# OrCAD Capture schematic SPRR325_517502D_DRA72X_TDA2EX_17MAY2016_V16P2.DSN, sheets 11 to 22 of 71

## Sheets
11 SH15 - SoC CLOCKS: size B; rev: A
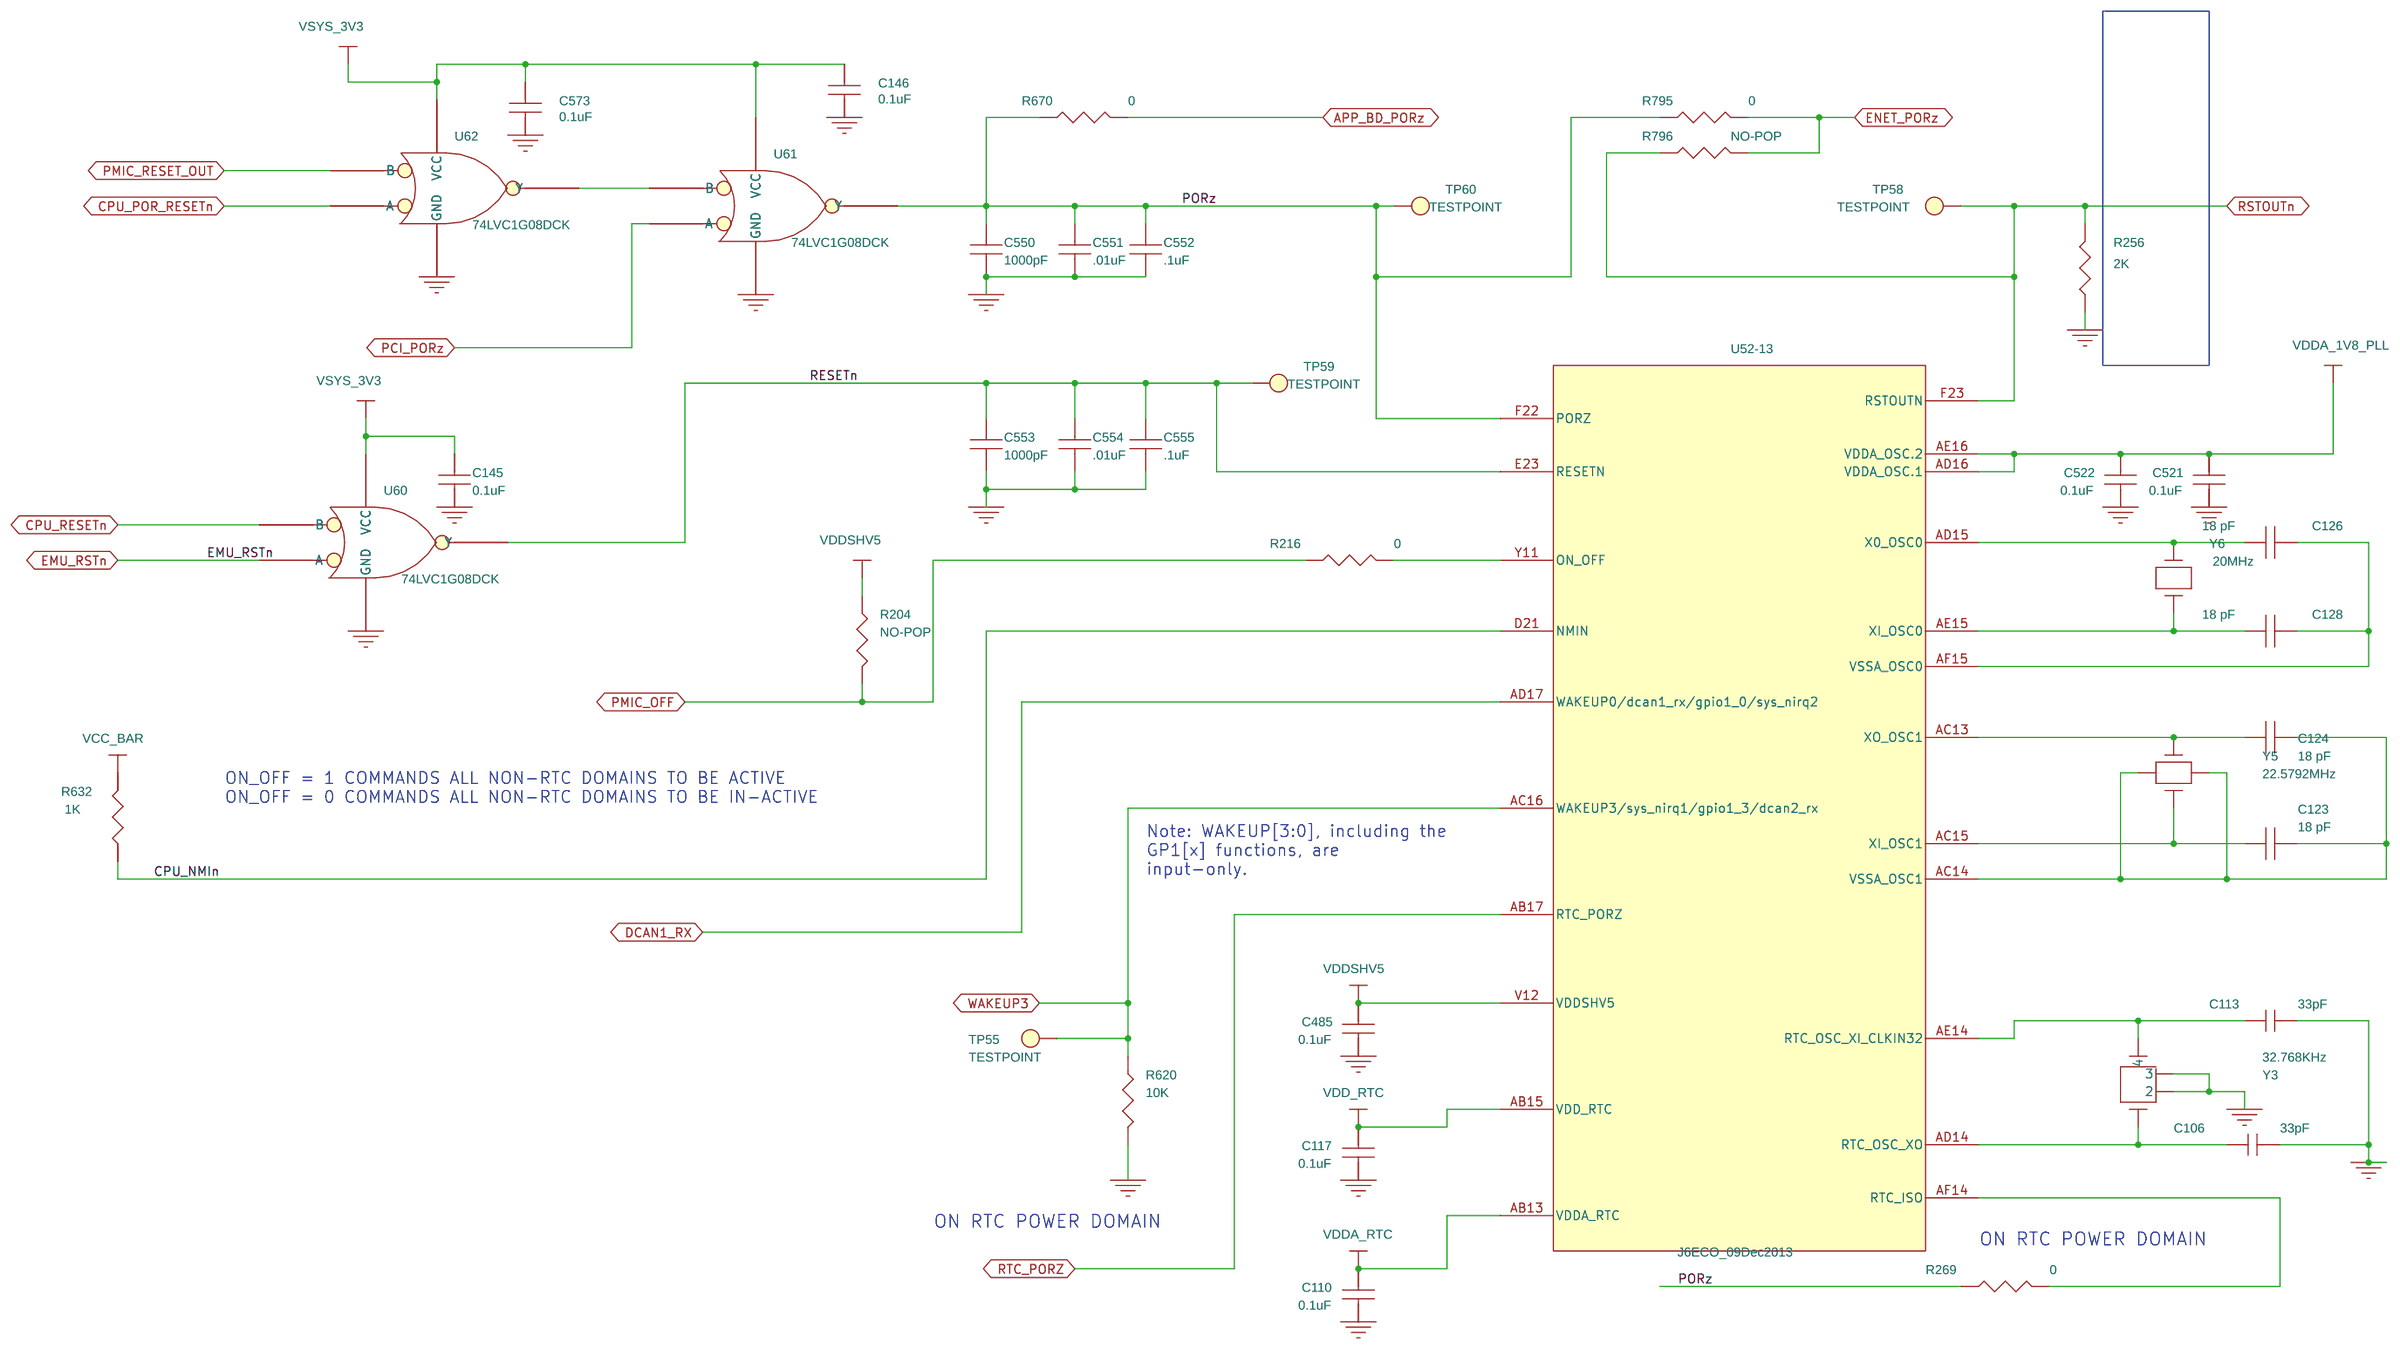
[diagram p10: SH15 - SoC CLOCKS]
12 SH16 - SoC INTERNAL LDOS: size B; rev: A
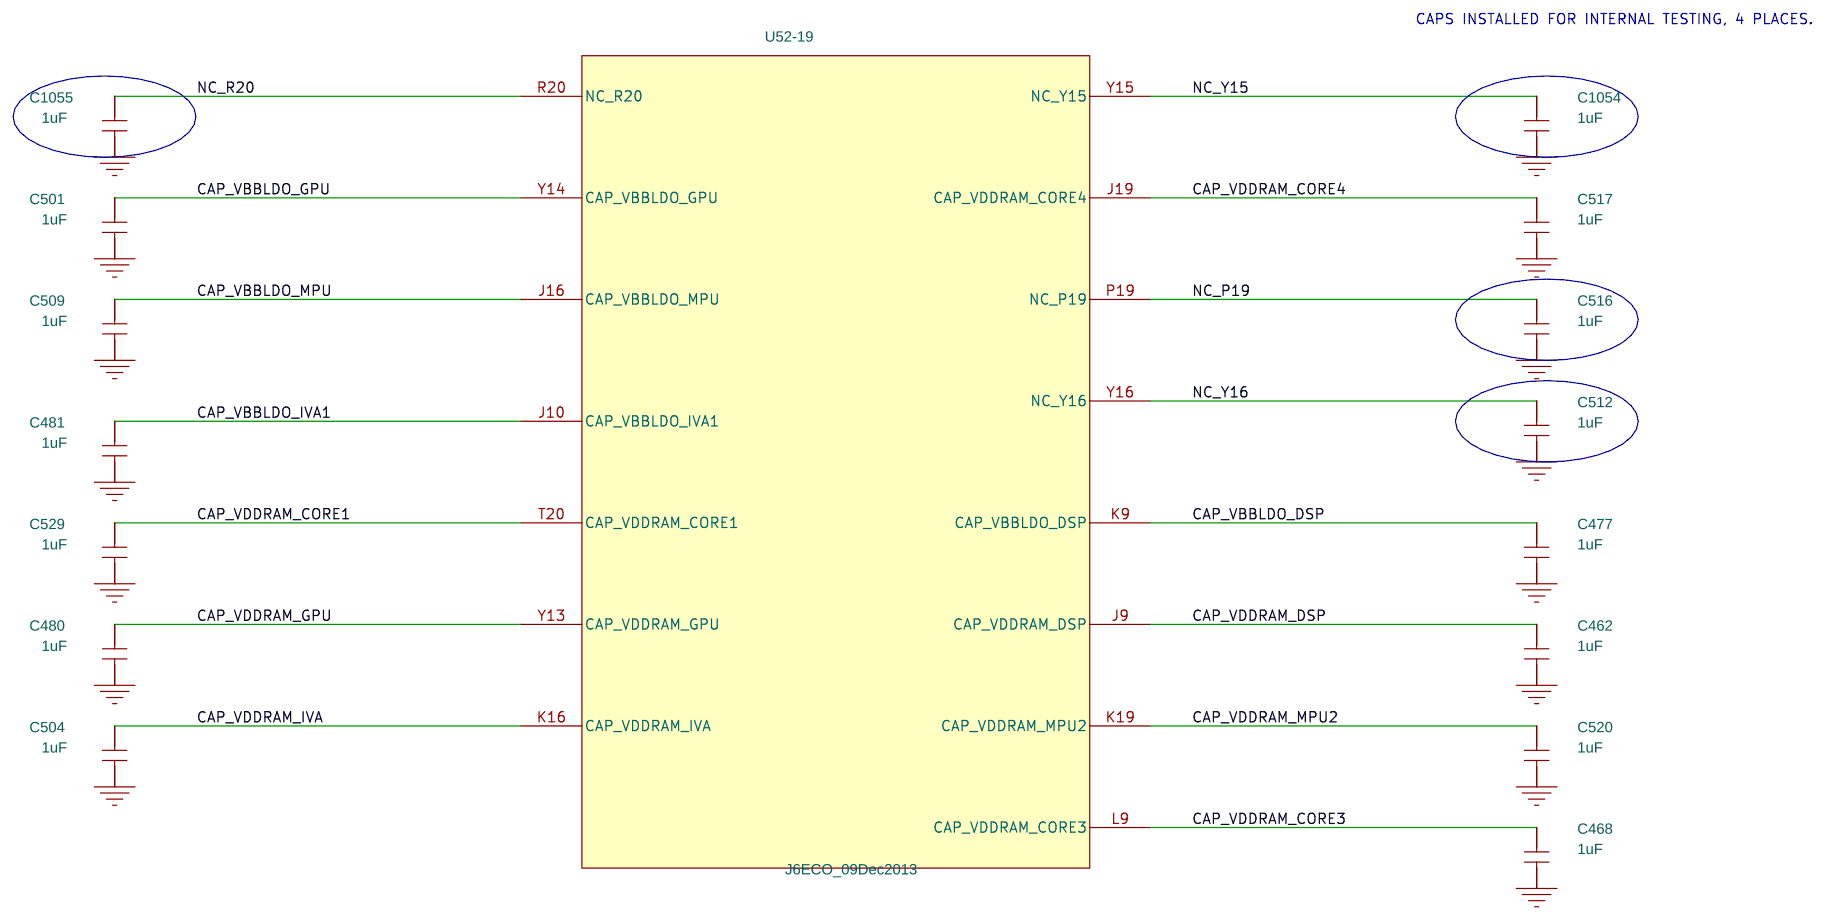
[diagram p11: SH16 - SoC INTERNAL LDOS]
13 SH17 - SoC IO POWER: size B; rev: A
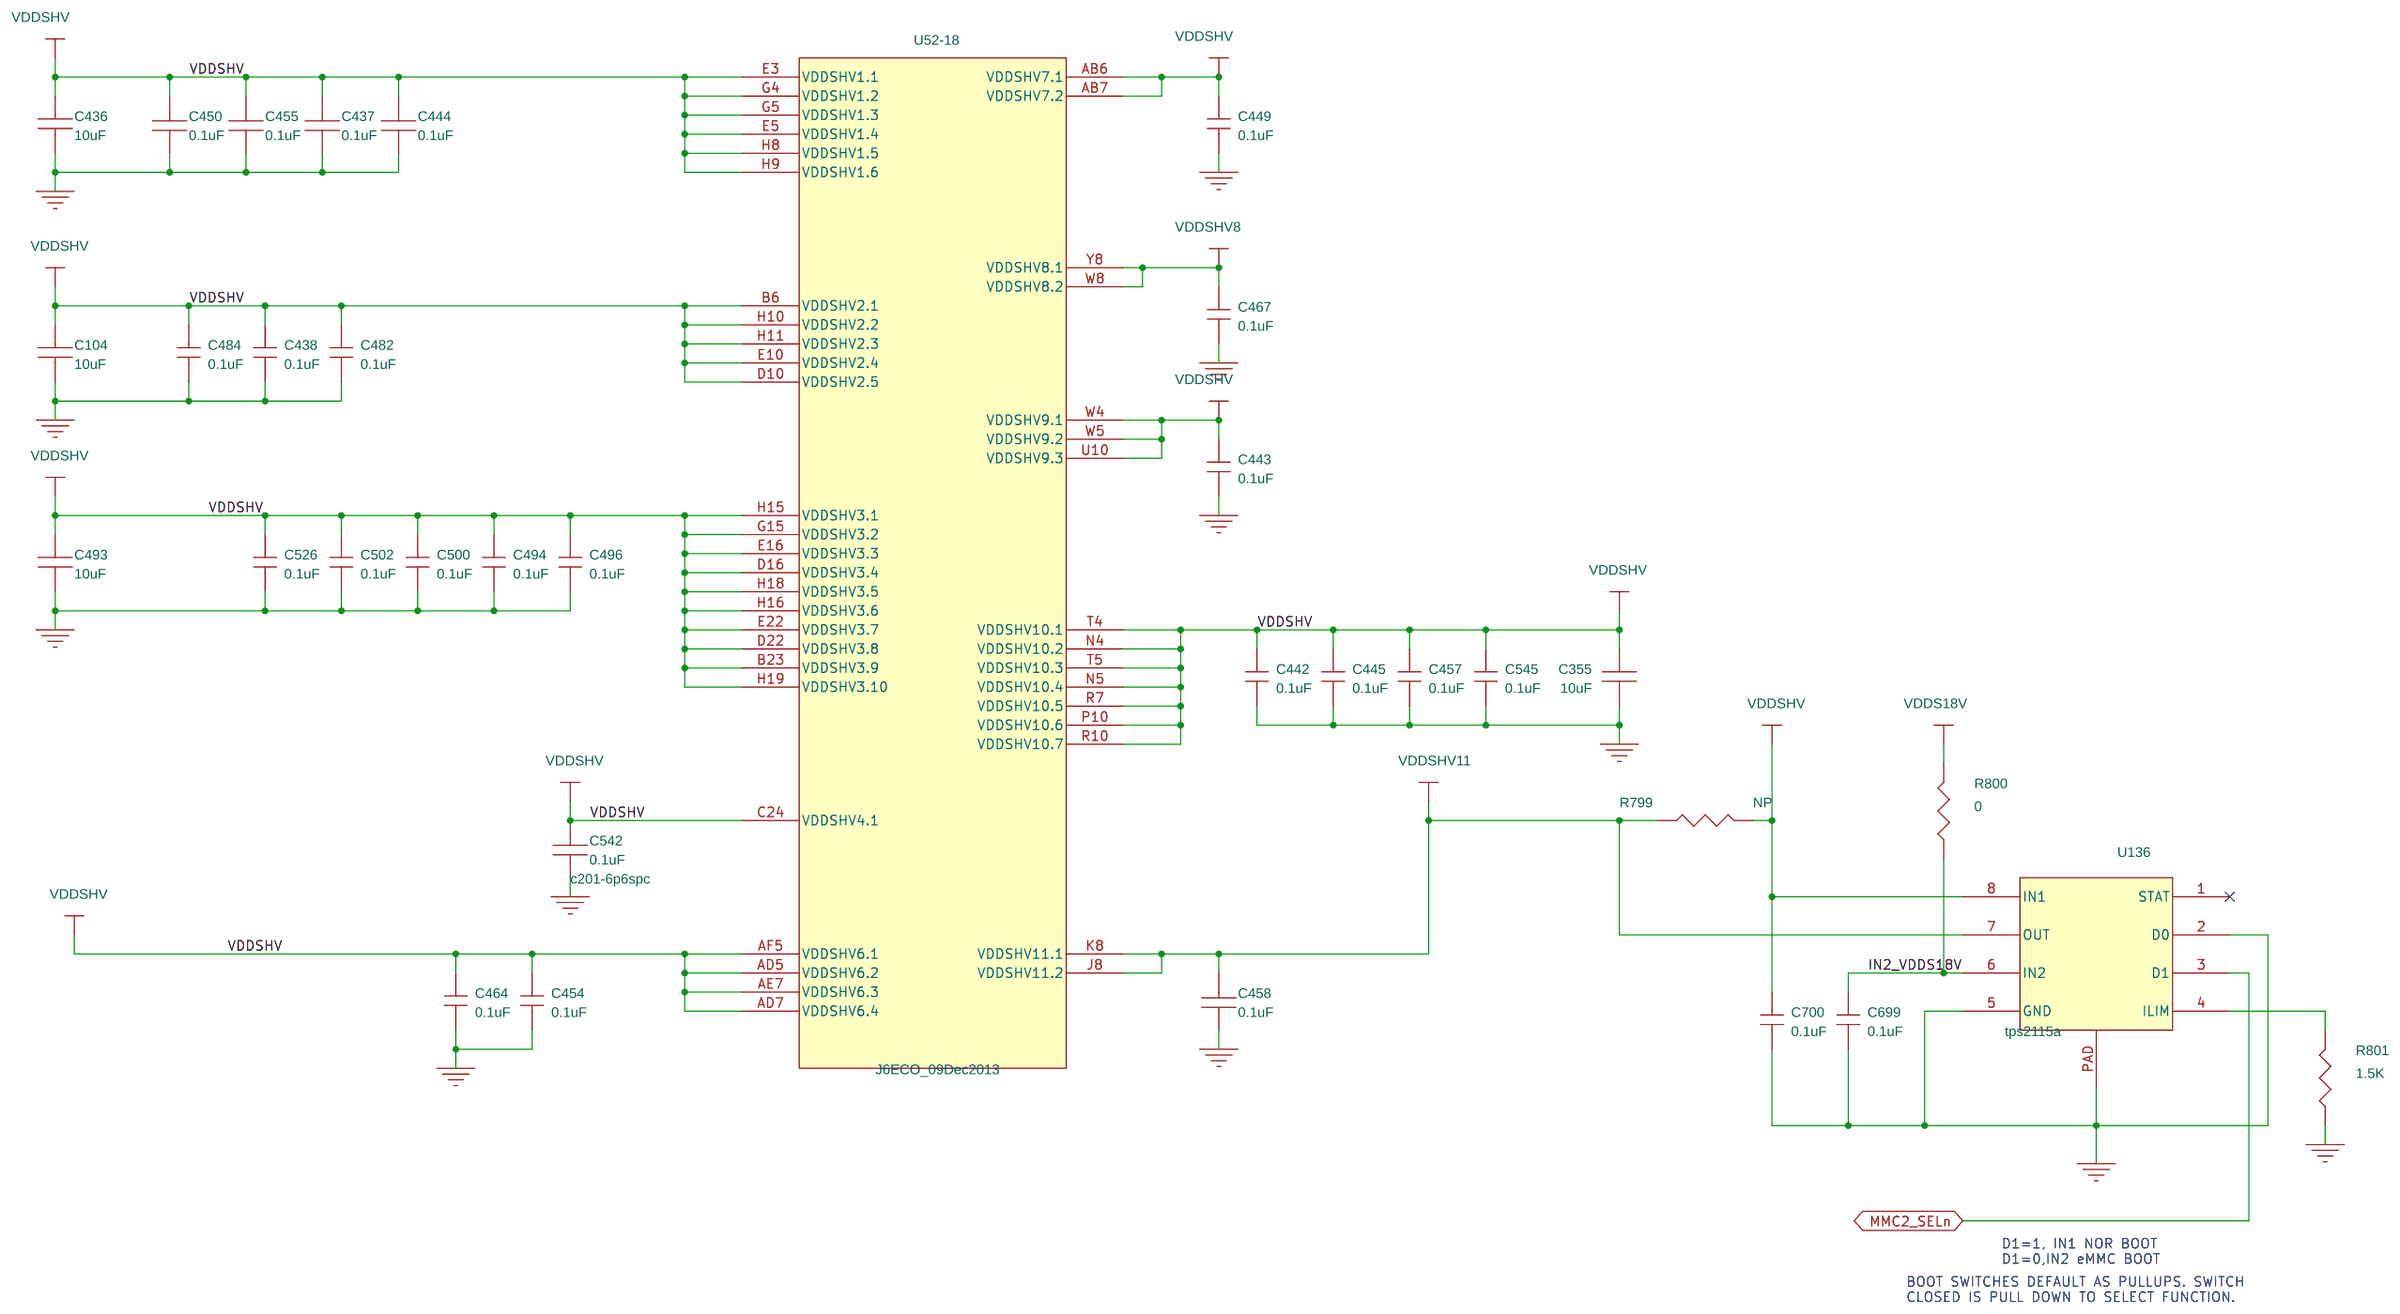
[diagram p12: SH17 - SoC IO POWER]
14 SH18 - SoC POWER 1V8: size B; rev: A
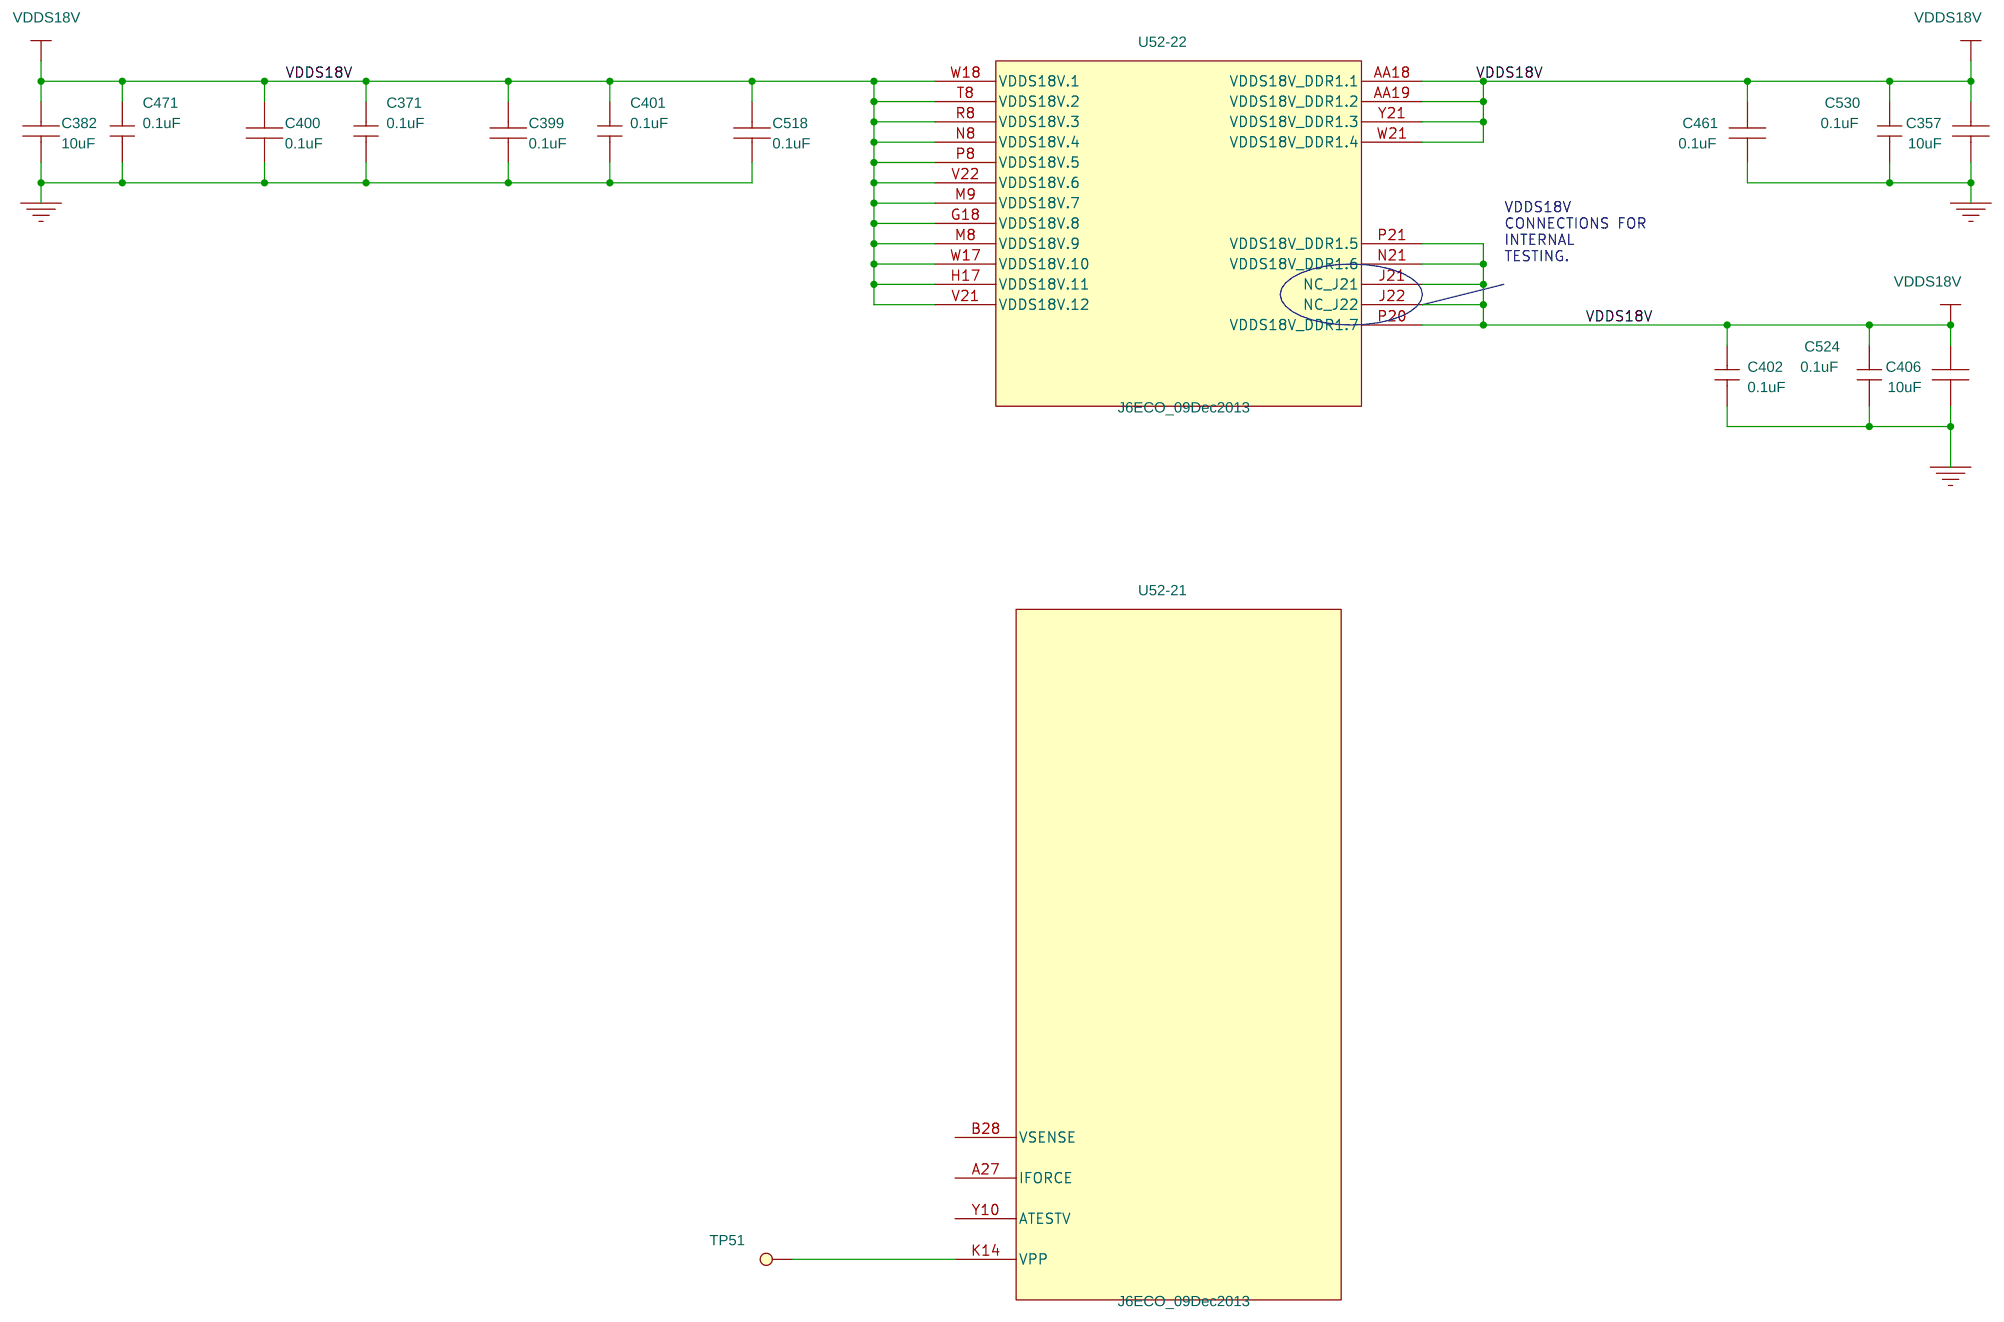
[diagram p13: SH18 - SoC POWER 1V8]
15 SH19 - SoC DDR POWER: size B; rev: A
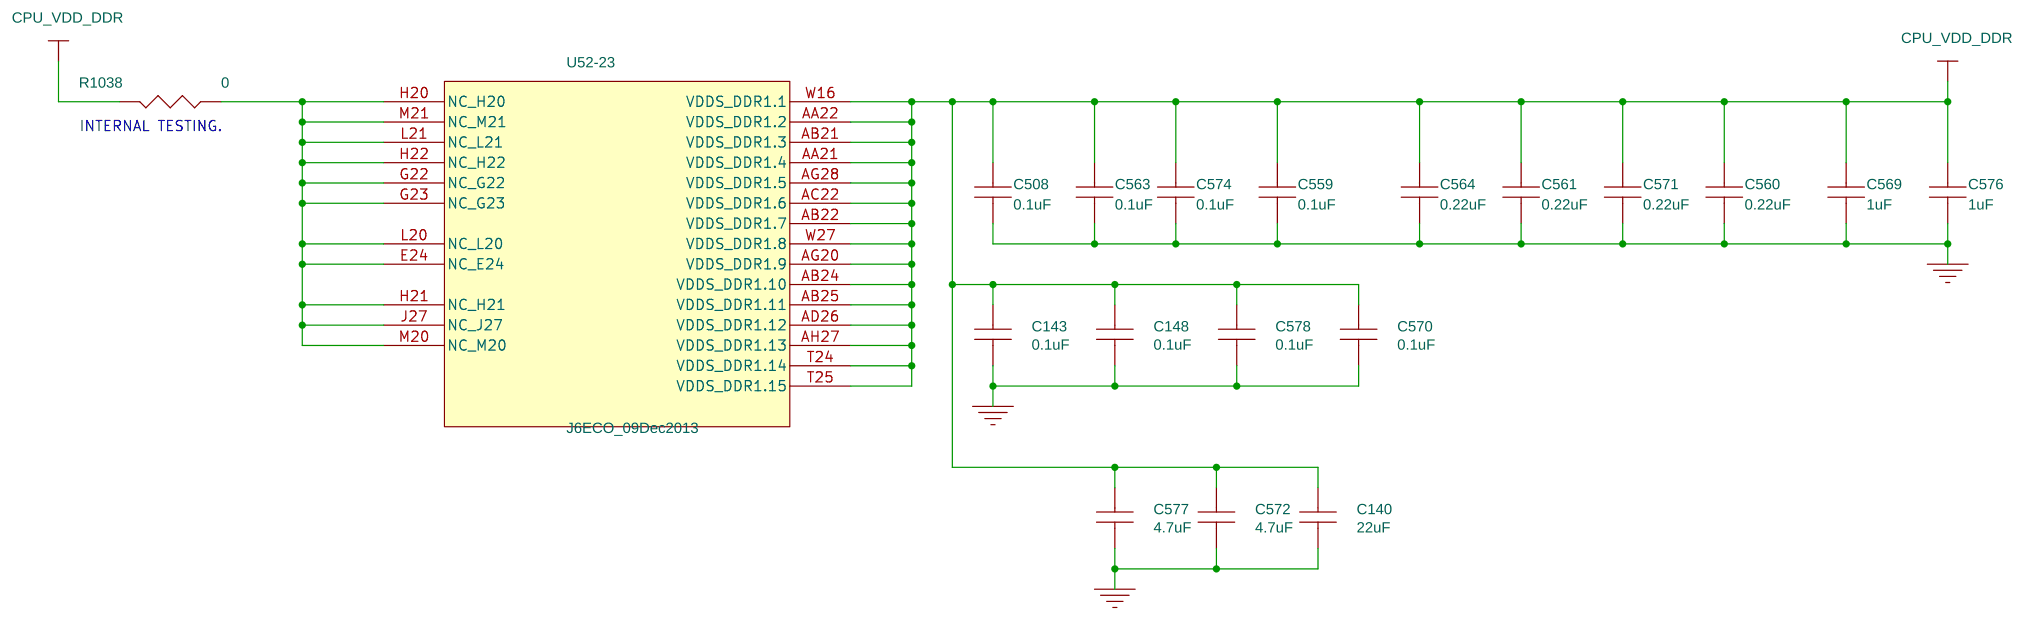
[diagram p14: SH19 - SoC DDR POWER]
16 SH20 - SoC 1V8A: size B; rev: A
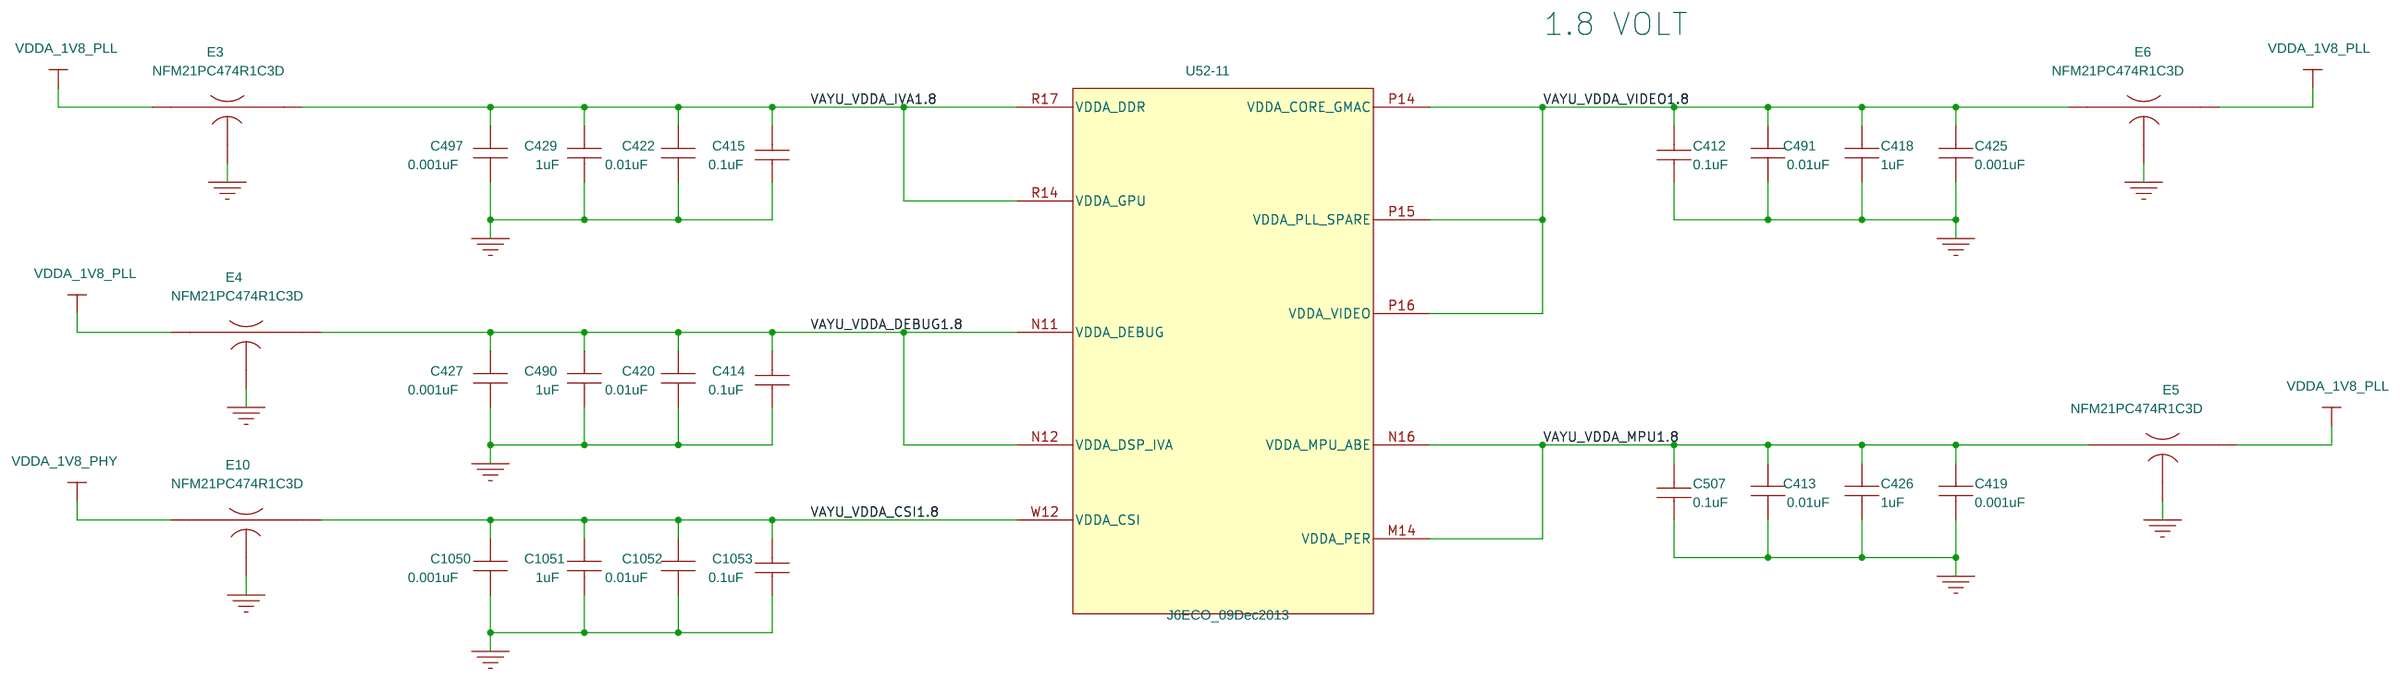
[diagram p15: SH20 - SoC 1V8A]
17 SH21 - SoC CORE POWER: size B; rev: A
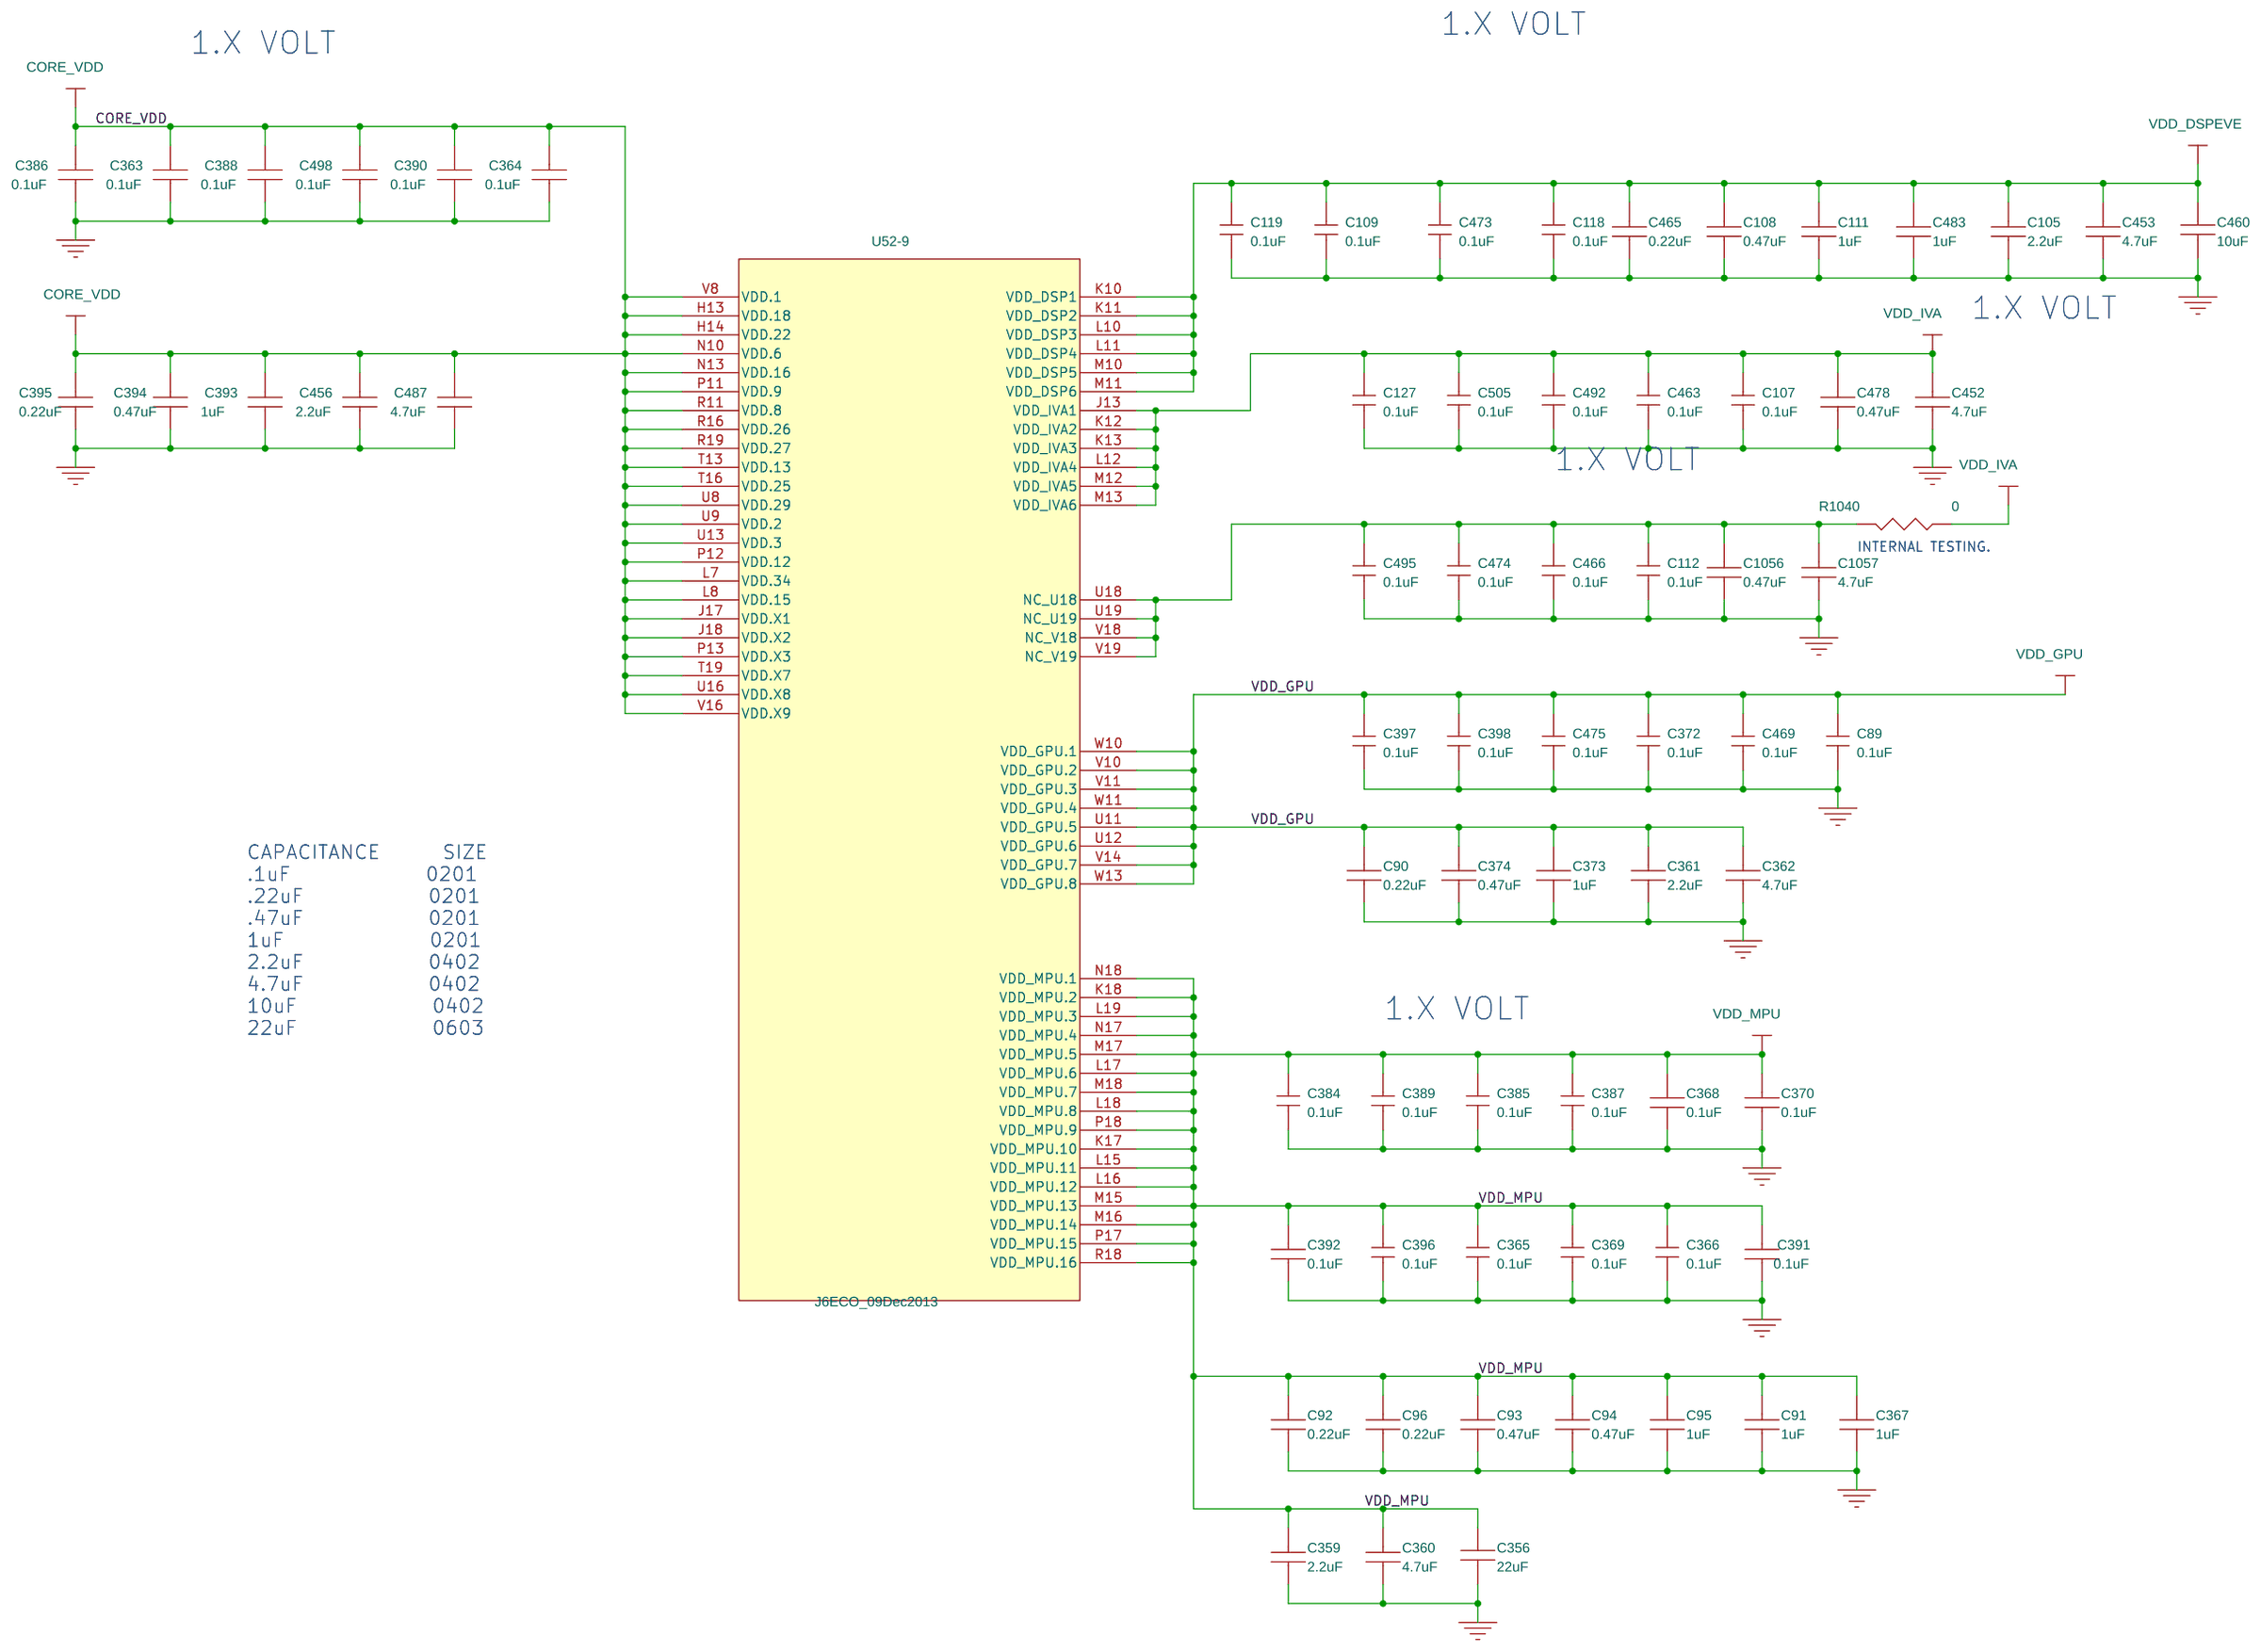
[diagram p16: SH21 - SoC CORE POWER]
18 SH22 - SoC GROUND PINS: size B; rev: A
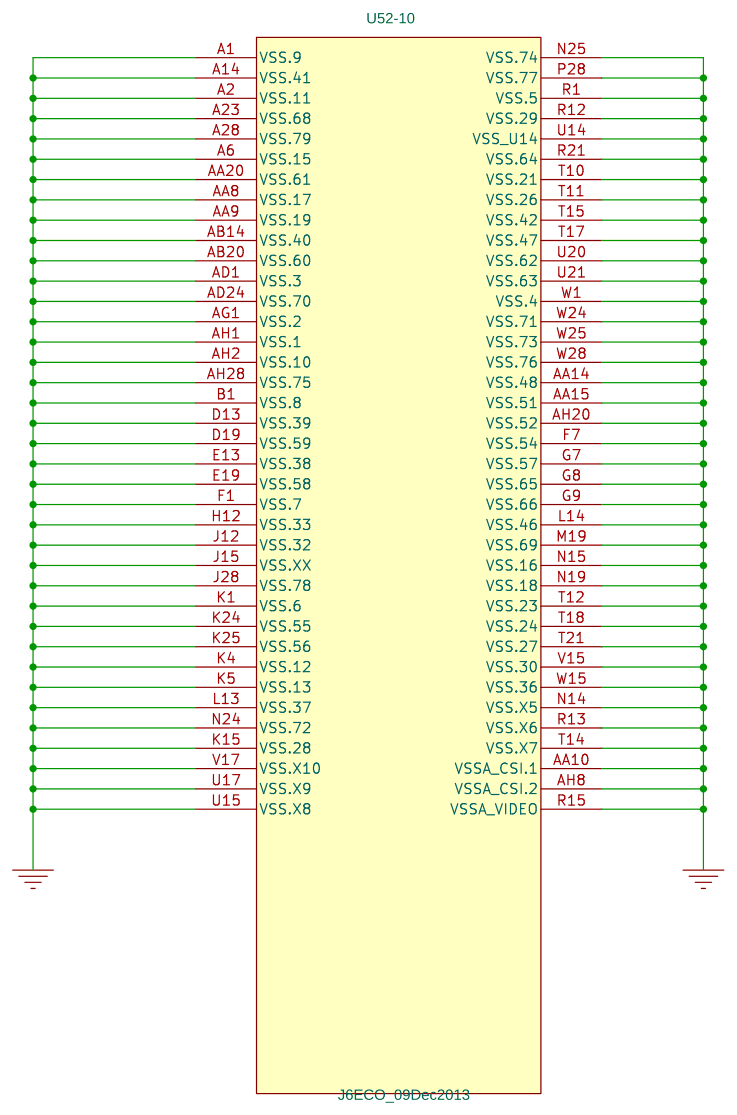
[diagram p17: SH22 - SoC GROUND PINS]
19 SH23 - DDR3 EMIF1 TESTPOINTS: size B; rev: B
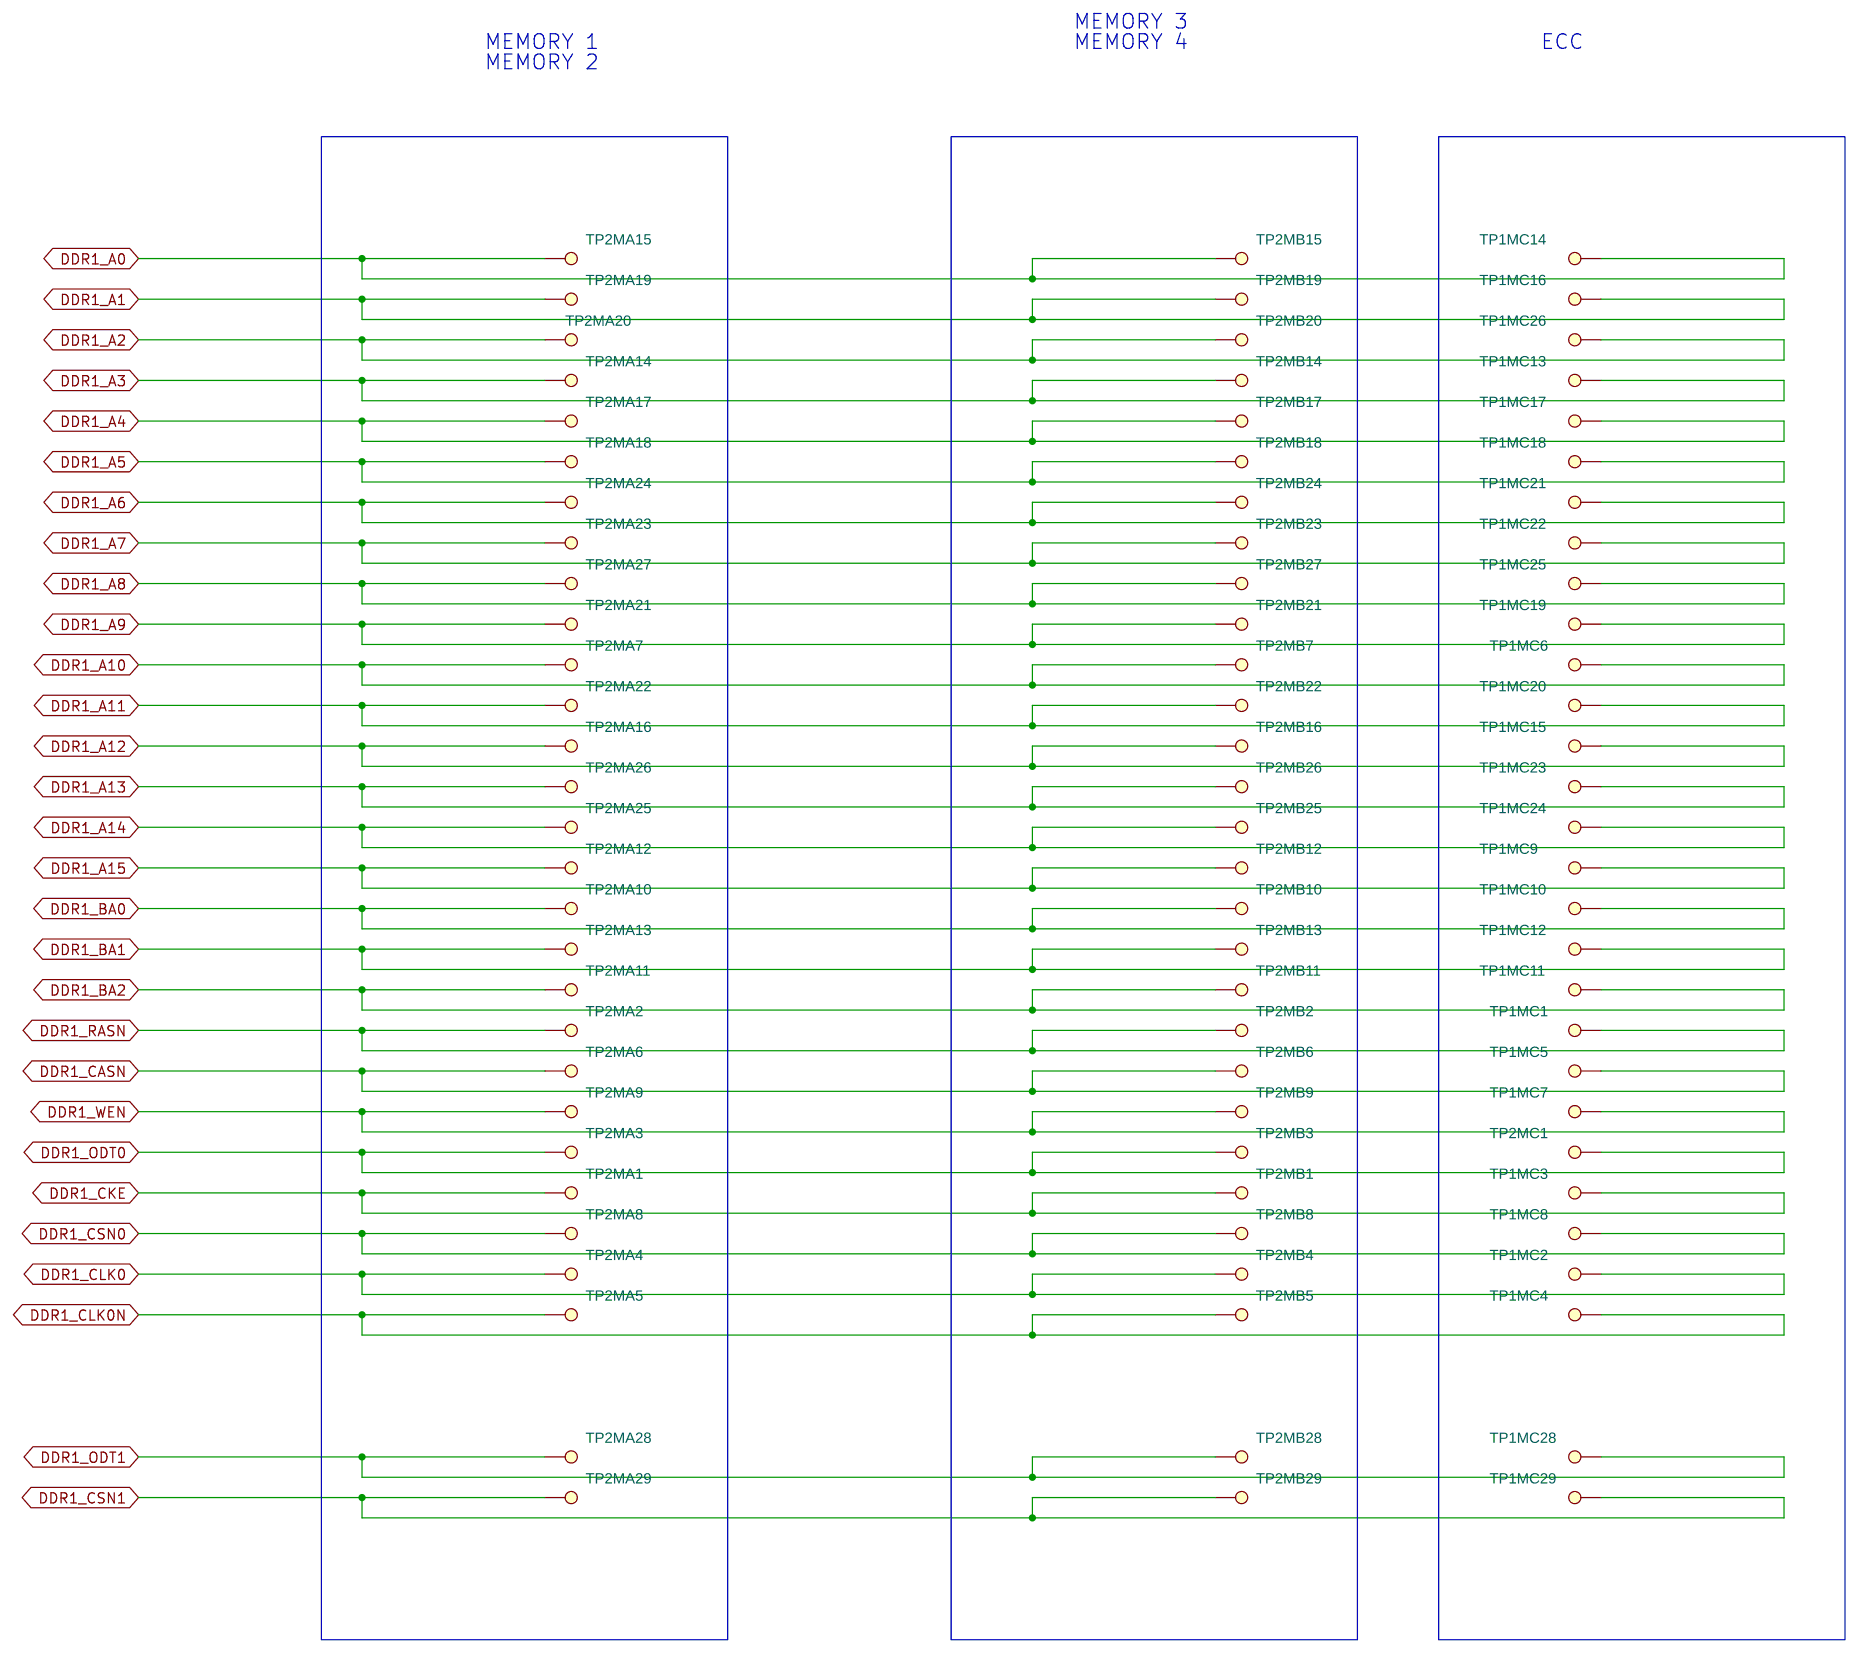
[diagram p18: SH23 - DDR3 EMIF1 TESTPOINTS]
20 SH24 - DDR3  BANK 1 ECC: size B; rev: C
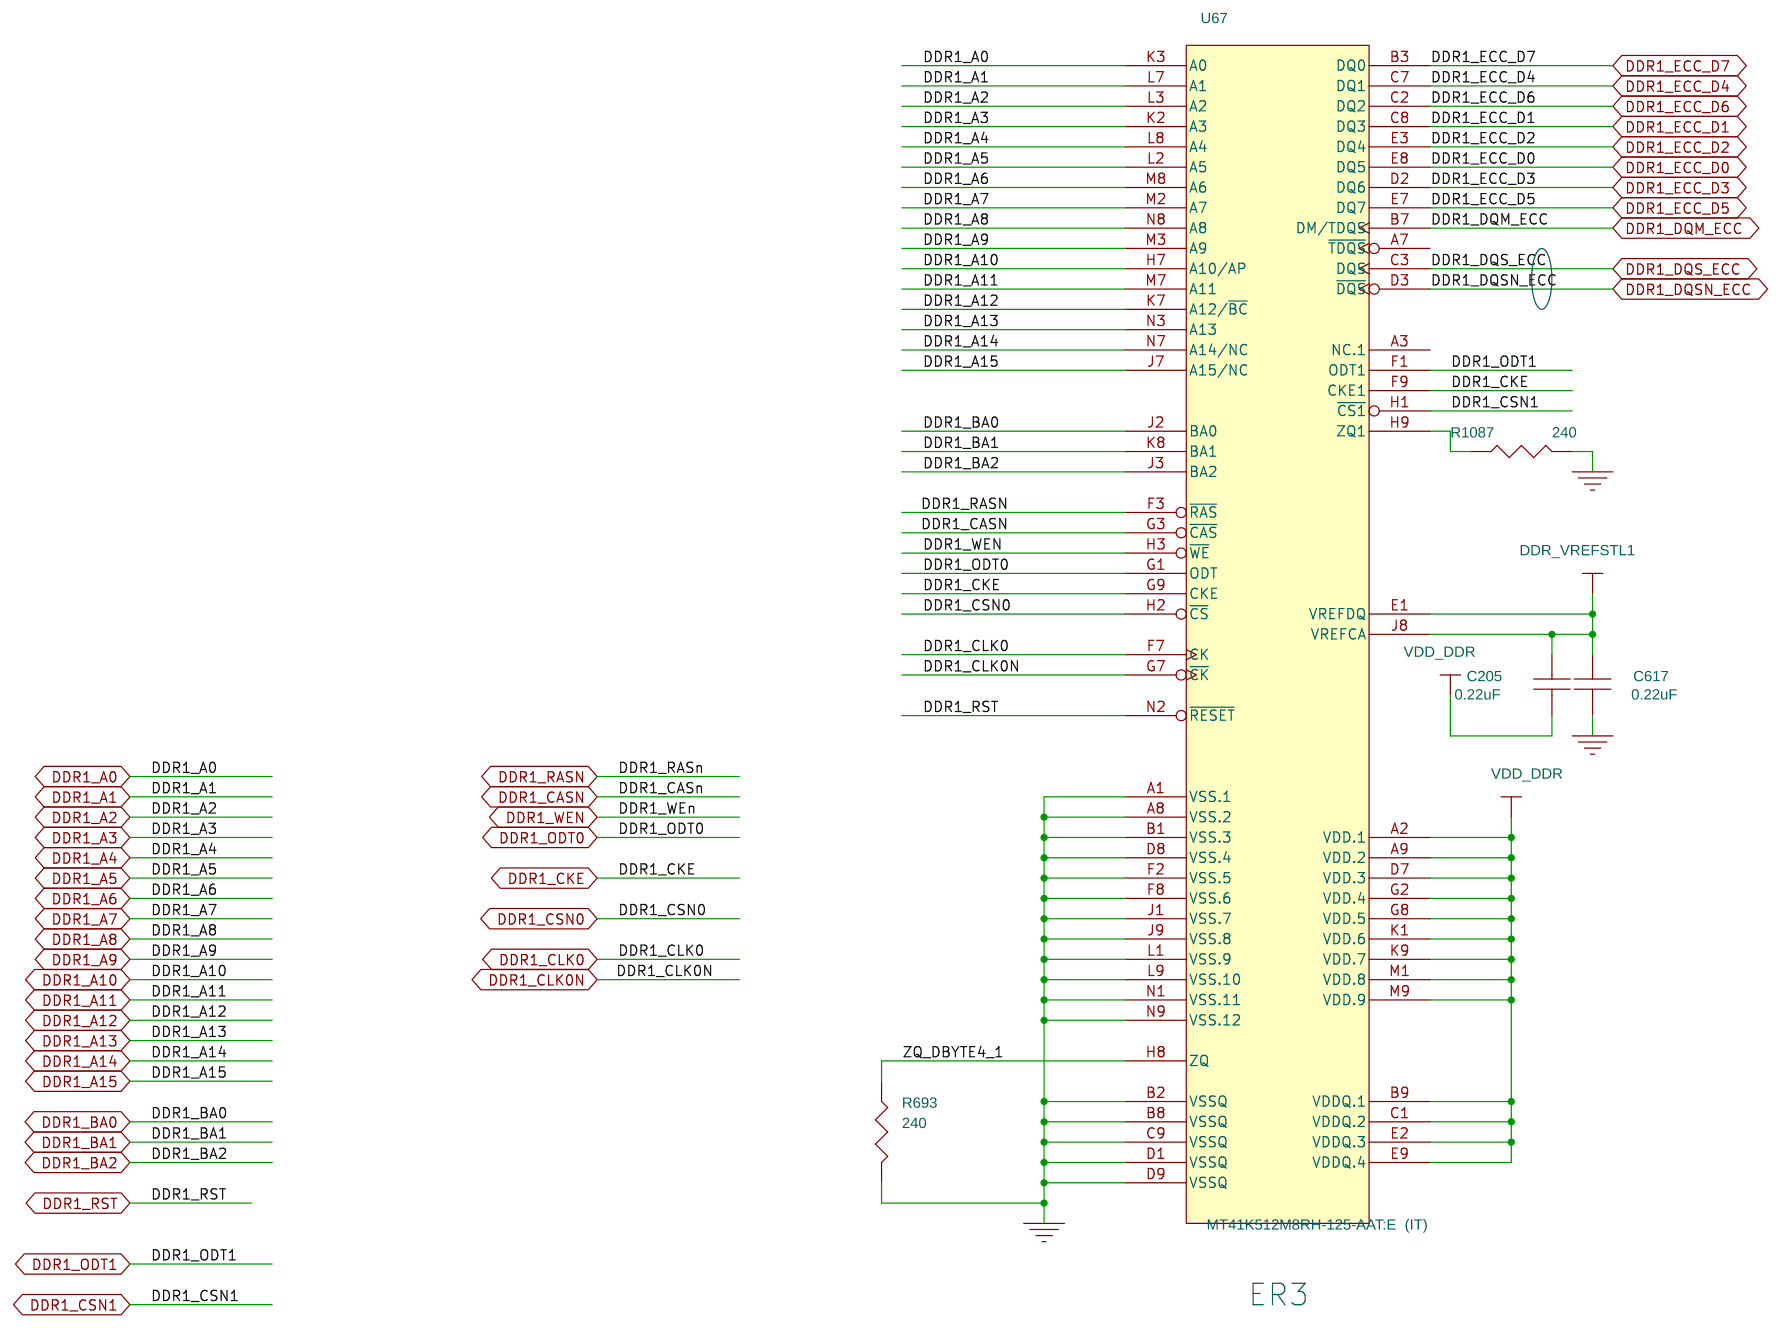
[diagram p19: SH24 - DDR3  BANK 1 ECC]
21 SH25 - DDR3 MEMORY BANK 1: size B; rev: C
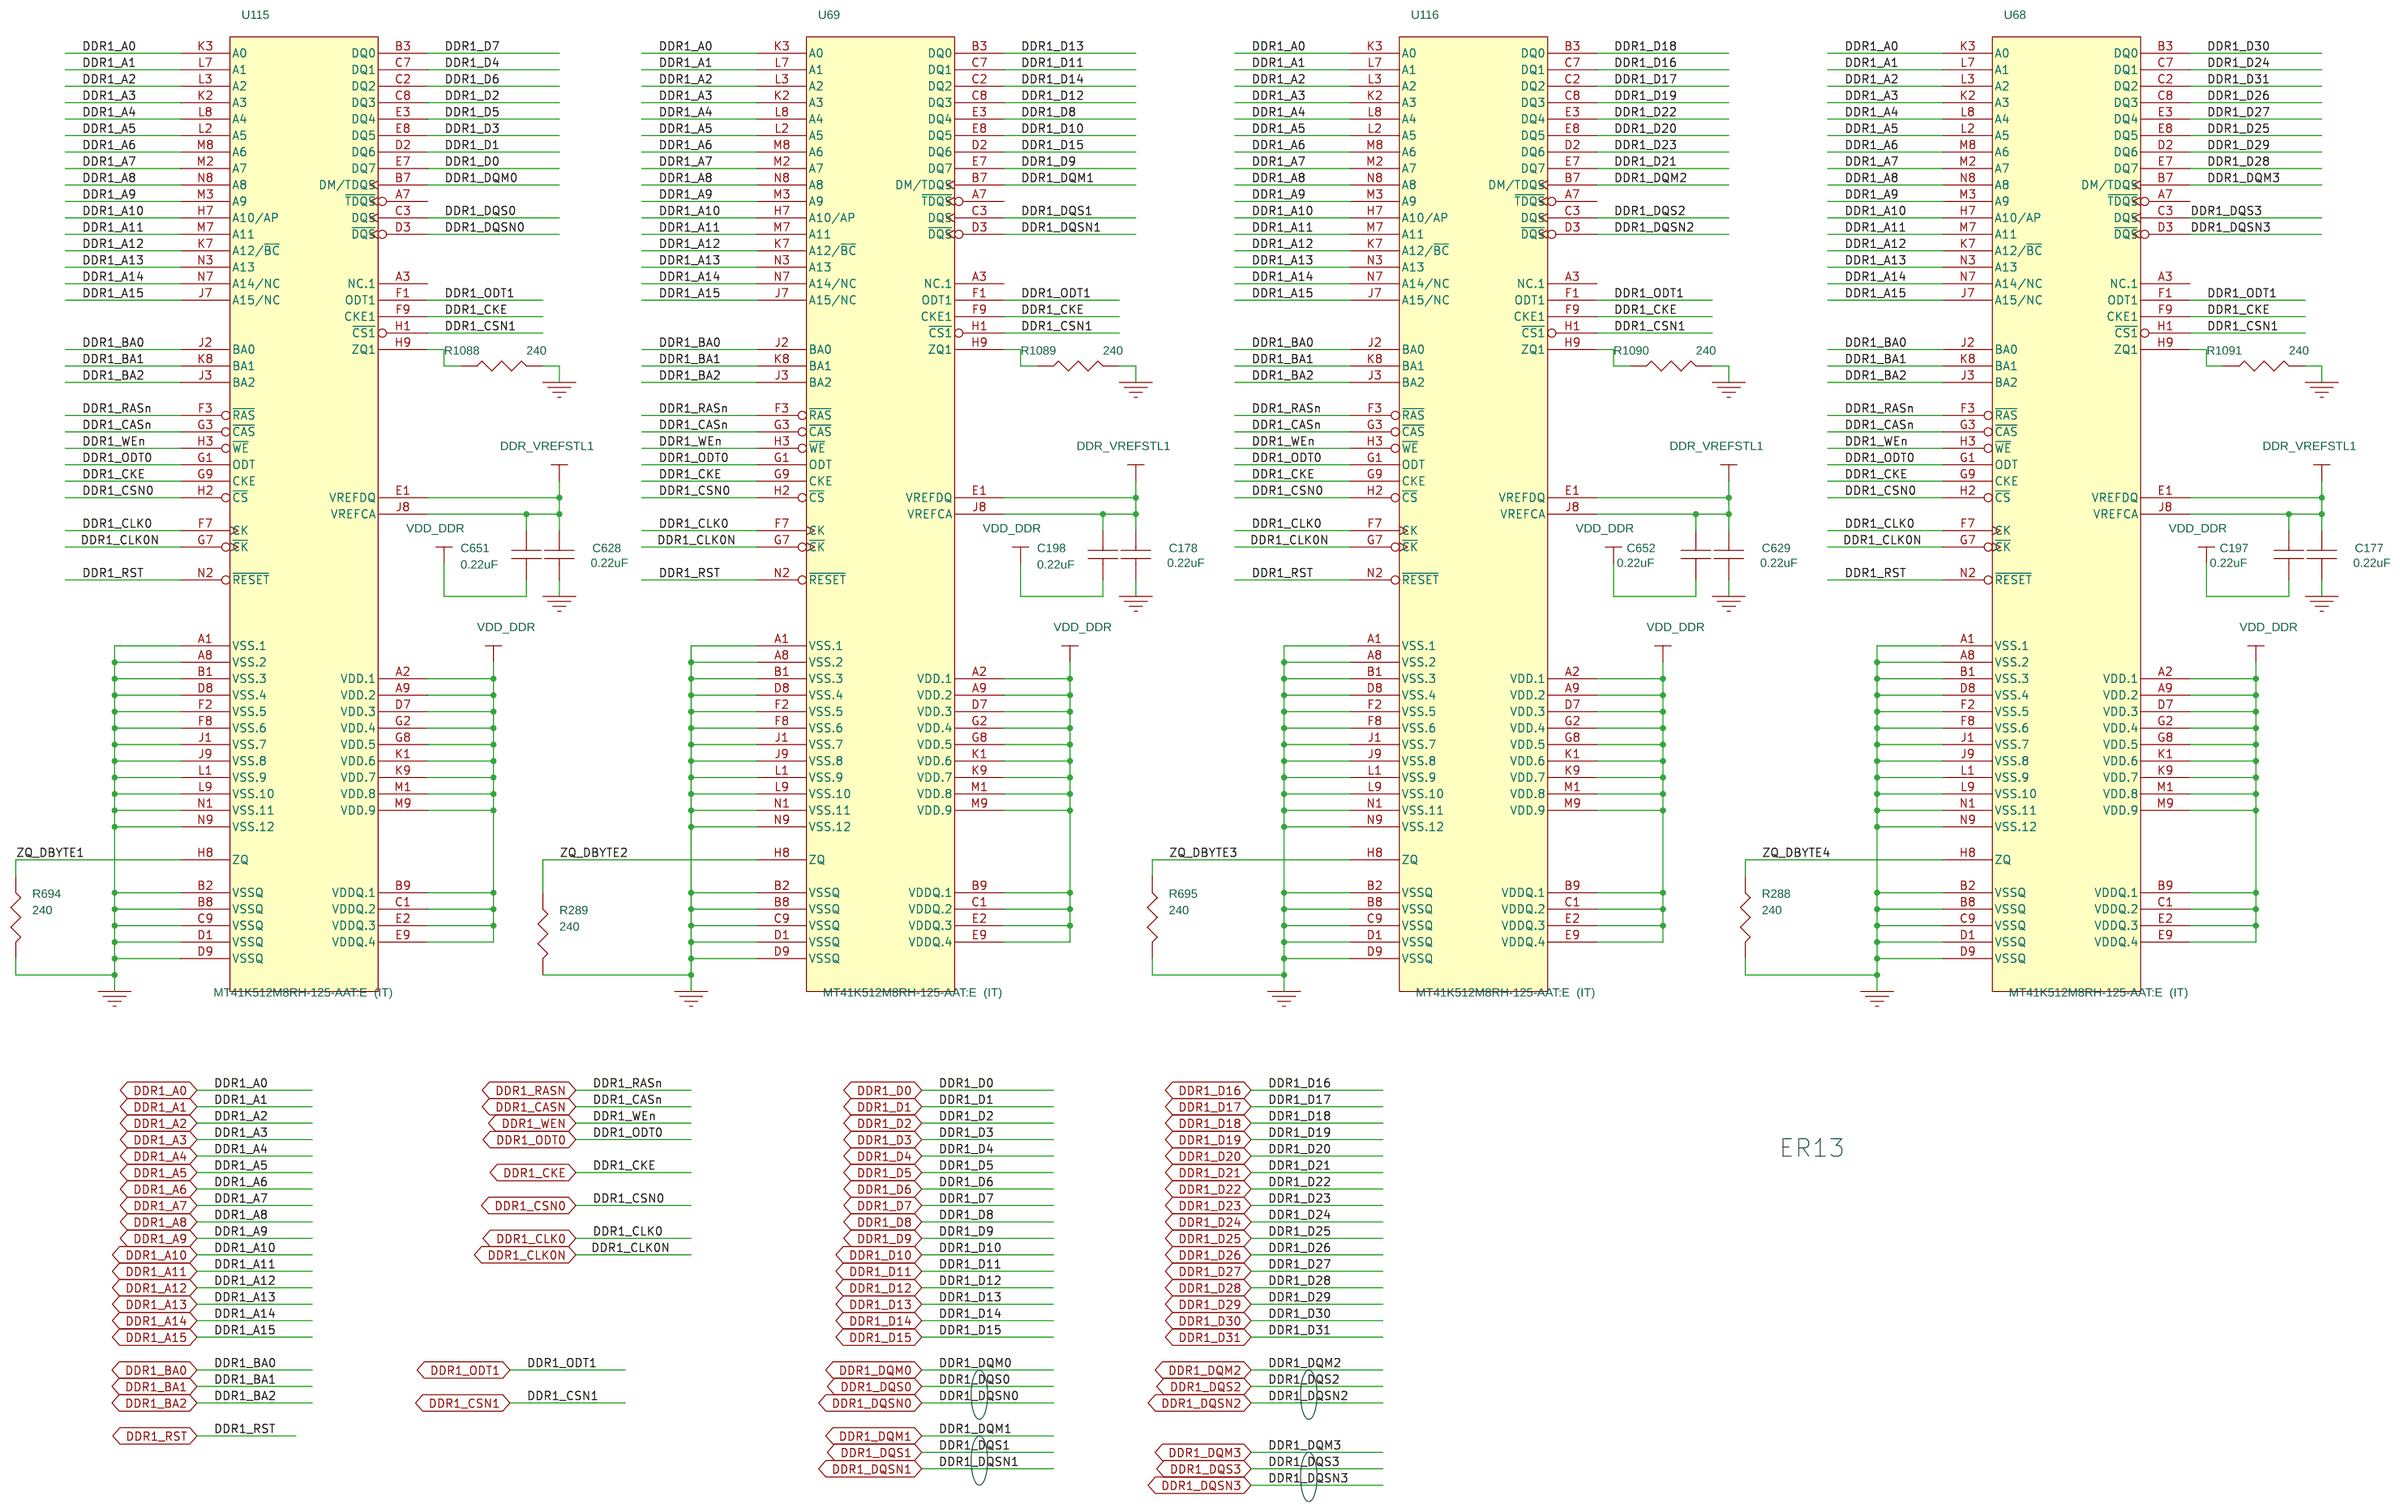
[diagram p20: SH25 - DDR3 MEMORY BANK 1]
22 SH26 - DDR3 MEMORY CAPS BANK 1: size B; rev: A
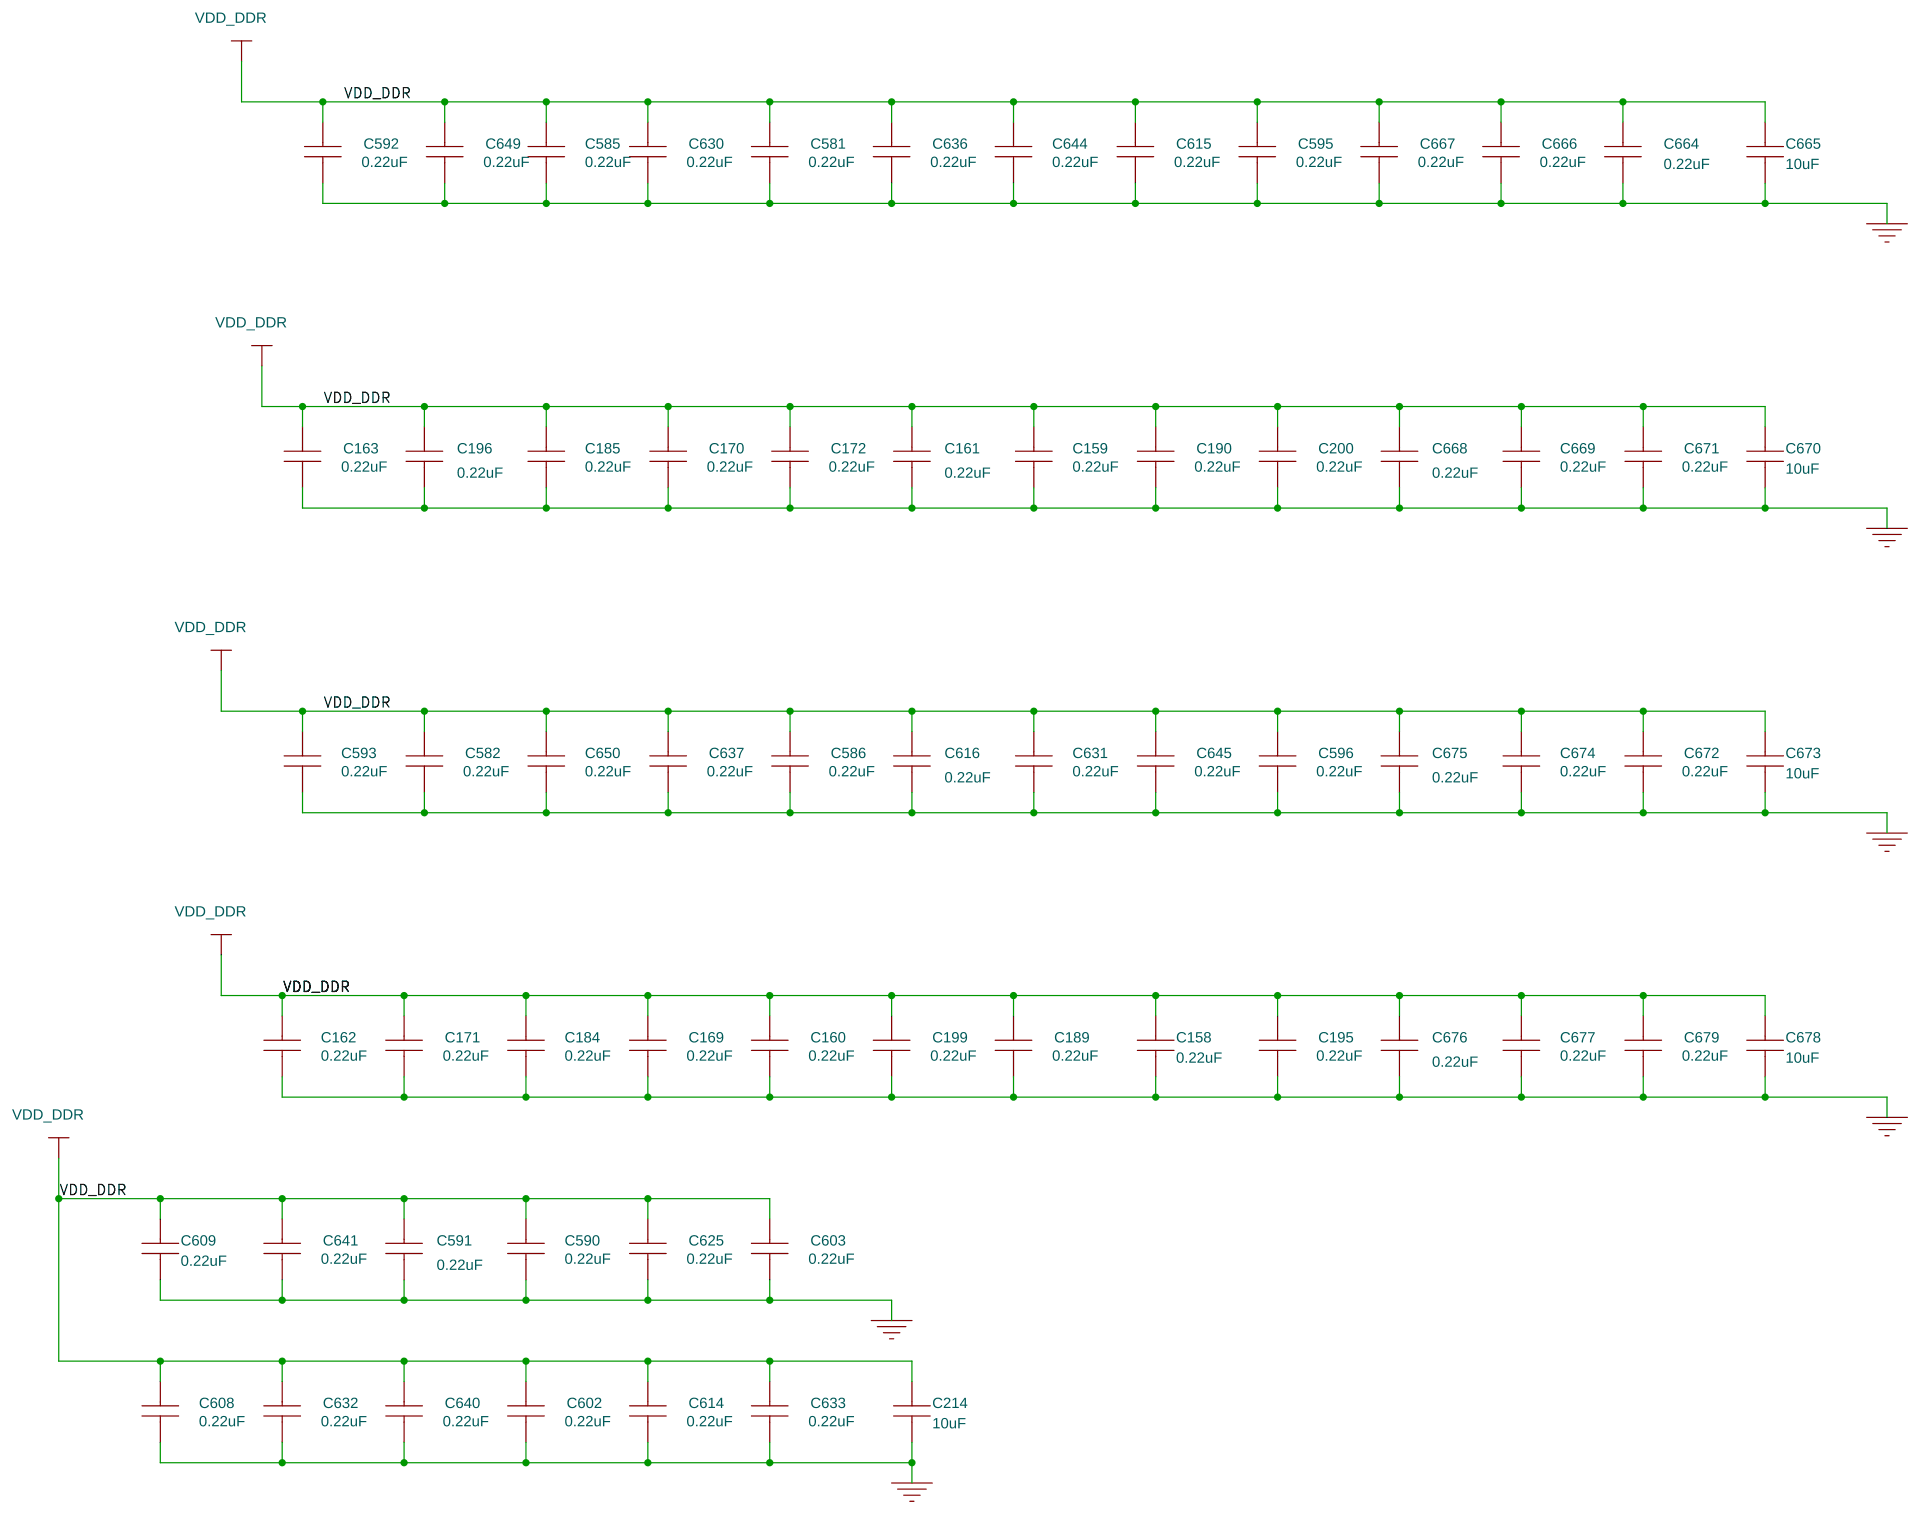
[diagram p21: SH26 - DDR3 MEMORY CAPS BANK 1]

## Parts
sheet SH15 - SoC CLOCKS
C106  33pF  [c402-25]
C110  0.1uF  [c201-6p6spc]
C113  33pF  [c402-25]
C117  0.1uF  [c201-6p6spc]
C123  18 pF  [c402-25]
C124  18 pF  [c402-25]
C126  18 pF  [c402-25]
C128  18 pF  [c402-25]
C145  0.1uF  [c402-25]
C146  0.1uF  [c402-25]
C485  0.1uF  [c201-6p6spc]
C521  0.1uF  [c201-6p6spc]
C522  0.1uF  [c201-6p6spc]
C550  1000pF  [c201-6p6spc]
C551  .01uF  [c201-6p6spc]
C552  .1uF  [c201-6p6spc]
C553  1000pF  [c201-6p6spc]
C554  .01uF  [c201-6p6spc]
C555  .1uF  [c201-6p6spc]
C573  0.1uF  [c402-25]
R204  NO-POP  [r201-6p6spc]
R216  0  [r201-6p6spc]
R256  2K  [r402-25]
R269  0  [r201-6p6spc]
R620  10K  [r201-6p6spc]
R632  1K  [r201-6p6spc]
R670  0  [r201-6p6spc]
R795  0  [r402-25]
R796  NO-POP  [r402-25]
TP55  TESTPOINT  [tp-30RD13]
TP58  TESTPOINT  [tp-30RD13]
TP59  TESTPOINT  [tp-30RD13]
TP60  TESTPOINT  [tp-30RD13]
U60  74LVC1G08DCK  [dck-5]
U61  74LVC1G08DCK  [dck-5]
U62  74LVC1G08DCK  [dck-5]
Y3  32.768KHz  [xtal4-23x47-ssp-t7]
Y5  22.5792MHz  [xtal4-55x87]
Y6  20MHz  [xtal2-75x94]
sheet SH16 - SoC INTERNAL LDOS
C462  1uF  [c402-25]
C468  1uF  [c402-25]
C477  1uF  [c402-25]
C480  1uF  [c402-25]
C481  1uF  [c402-25]
C501  1uF  [c402-25]
C504  1uF  [c402-25]
C509  1uF  [c402-25]
C512  1uF  [c402-25]
C516  1uF  [c402-25]
C517  1uF  [c402-25]
C520  1uF  [c402-25]
C529  1uF  [c402-25]
C1054  1uF  [c402-25]
C1055  1uF  [c402-25]
sheet SH17 - SoC IO POWER
C104  10uF  [c603-35x45]
C355  10uF  [c603-35x45]
C436  10uF  [c603-35x45]
C437  0.1uF  [c201-6p6spc]
C438  0.1uF  [c201-6p6spc]
C442  0.1uF  [c201-6p6spc]
C443  0.1uF  [c201-6p6spc]
C444  0.1uF  [c201-6p6spc]
C445  0.1uF  [c201-6p6spc]
C449  0.1uF  [c201-6p6spc]
C450  0.1uF  [c201-6p6spc]
C454  0.1uF  [c201-6p6spc]
C455  0.1uF  [c201-6p6spc]
C457  0.1uF  [c201-6p6spc]
C458  0.1uF  [c201-6p6spc]
C464  0.1uF  [c201-6p6spc]
C467  0.1uF  [c201-6p6spc]
C482  0.1uF  [c201-6p6spc]
C484  0.1uF  [c201-6p6spc]
C493  10uF  [c603-35x45]
C494  0.1uF  [c201-6p6spc]
C496  0.1uF  [c201-6p6spc]
C500  0.1uF  [c201-6p6spc]
C502  0.1uF  [c201-6p6spc]
C526  0.1uF  [c201-6p6spc]
C542  0.1uF  [c201-6p6spc]
C545  0.1uF  [c201-6p6spc]
C699  0.1uF  [c201-6p6spc]
C700  0.1uF  [c201-6p6spc]
R799  NP  [r402-25]
R800  0  [r402-25]
R801  1.5K  [r402-25]
U52  J6ECO_09Dec2013  [sktbga-zkk-6334-p760]  (sections -1,-10,-11,-12,-13,-14,-15,-16,-17,-18,-19,-2,-20,-21,-22,-23,-3,-4,-5,-6,-7,-8,-9)
U136  tps2115a  [drb8-14x33-pad]
sheet SH18 - SoC POWER 1V8
C357  10uF  [c603-35x45]
C371  0.1uF  [c201-6p6spc]
C382  10uF  [c603-35x45]
C399  0.1uF  [c201-6p6spc]
C400  0.1uF  [c201-6p6spc]
C401  0.1uF  [c201-6p6spc]
C402  0.1uF  [c201-6p6spc]
C406  10uF  [c603-35x45]
C461  0.1uF  [c201-6p6spc]
C471  0.1uF  [c201-6p6spc]
C518  0.1uF  [c201-6p6spc]
C524  0.1uF  [c201-6p6spc]
C530  0.1uF  [c201-6p6spc]
TP51  TestPoint1  [tp1-18rd8]
sheet SH19 - SoC DDR POWER
C140  22uF  [c603-35x45]
C143  0.1uF  [c201-6p6spc]
C148  0.1uF  [c201-6p6spc]
C508  0.1uF  [c201-6p6spc]
C559  0.1uF  [c201-6p6spc]
C560  0.22uF  [c201-6p6spc]
C561  0.22uF  [c201-6p6spc]
C563  0.1uF  [c201-6p6spc]
C564  0.22uF  [c201-6p6spc]
C569  1uF  [c402-25]
C570  0.1uF  [c201-6p6spc]
C571  0.22uF  [c201-6p6spc]
C572  4.7uF  [c402-25]
C574  0.1uF  [c201-6p6spc]
C576  1uF  [c402-25]
C577  4.7uF  [c402-25]
C578  0.1uF  [c201-6p6spc]
R1038  0  [r402-25]
sheet SH20 - SoC 1V8A
C412  0.1uF  [c201-6p6spc]
C413  0.01uF  [c201-6p6spc]
C414  0.1uF  [c201-6p6spc]
C415  0.1uF  [c201-6p6spc]
C418  1uF  [c201-6p6spc]
C419  0.001uF  [c201-6p6spc]
C420  0.01uF  [c201-6p6spc]
C422  0.01uF  [c201-6p6spc]
C425  0.001uF  [c201-6p6spc]
C426  1uF  [c201-6p6spc]
C427  0.001uF  [c201-6p6spc]
C429  1uF  [c201-6p6spc]
C490  1uF  [c201-6p6spc]
C491  0.01uF  [c201-6p6spc]
C497  0.001uF  [c201-6p6spc]
C507  0.1uF  [c201-6p6spc]
C1050  0.001uF  [c201-6p6spc]
C1051  1uF  [c201-6p6spc]
C1052  0.01uF  [c201-6p6spc]
C1053  0.1uF  [c201-6p6spc]
E3  NFM21PC474R1C3D  [emi-NFM21p]
E4  NFM21PC474R1C3D  [emi-NFM21p]
E5  NFM21PC474R1C3D  [emi-NFM21p]
E6  NFM21PC474R1C3D  [emi-NFM21p]
E10  NFM21PC474R1C3D  [emi-NFM21p]
sheet SH21 - SoC CORE POWER
C89  0.1uF  [c201-6p6spc]
C90  0.22uF  [c201-6p6spc]
C91  1uF  [c201-6p6spc]
C92  0.22uF  [c201-6p6spc]
C93  0.47uF  [c201-6p6spc]
C94  0.47uF  [c201-6p6spc]
C95  1uF  [c201-6p6spc]
C96  0.22uF  [c201-6p6spc]
C105  2.2uF  [c402-25]
C107  0.1uF  [c201-6p6spc]
C108  0.47uF  [c201-6p6spc]
C109  0.1uF  [c201-6p6spc]
C111  1uF  [c201-6p6spc]
C112  0.1uF  [c201-6p6spc]
C118  0.1uF  [c201-6p6spc]
C119  0.1uF  [c201-6p6spc]
C127  0.1uF  [c201-6p6spc]
C356  22uF  [c603-35x45]
C359  2.2uF  [c402-25]
C360  4.7uF  [c402-25]
C361  2.2uF  [c402-25]
C362  4.7uF  [c402-25]
C363  0.1uF  [c201-6p6spc]
C364  0.1uF  [c201-6p6spc]
C365  0.1uF  [c201-6p6spc]
C366  0.1uF  [c201-6p6spc]
C367  1uF  [c201-6p6spc]
C368  0.1uF  [c201-6p6spc]
C369  0.1uF  [c201-6p6spc]
C370  0.1uF  [c201-6p6spc]
C372  0.1uF  [c201-6p6spc]
C373  1uF  [c201-6p6spc]
C374  0.47uF  [c201-6p6spc]
C384  0.1uF  [c201-6p6spc]
C385  0.1uF  [c201-6p6spc]
C386  0.1uF  [c201-6p6spc]
C387  0.1uF  [c201-6p6spc]
C388  0.1uF  [c201-6p6spc]
C389  0.1uF  [c201-6p6spc]
C390  0.1uF  [c201-6p6spc]
C391  0.1uF  [c201-6p6spc]
C392  0.1uF  [c201-6p6spc]
C393  1uF  [c201-6p6spc]
C394  0.47uF  [c201-6p6spc]
C395  0.22uF  [c201-6p6spc]
C396  0.1uF  [c201-6p6spc]
C397  0.1uF  [c201-6p6spc]
C398  0.1uF  [c201-6p6spc]
C452  4.7uF  [c402-25]
C453  4.7uF  [c402-25]
C456  2.2uF  [c402-25]
C460  10uF  [c402-25]
C463  0.1uF  [c201-6p6spc]
C465  0.22uF  [c201-6p6spc]
C466  0.1uF  [c201-6p6spc]
C469  0.1uF  [c201-6p6spc]
C473  0.1uF  [c201-6p6spc]
C474  0.1uF  [c201-6p6spc]
C475  0.1uF  [c201-6p6spc]
C478  0.47uF  [c201-6p6spc]
C483  1uF  [c201-6p6spc]
C487  4.7uF  [c402-25]
C492  0.1uF  [c201-6p6spc]
C495  0.1uF  [c201-6p6spc]
C498  0.1uF  [c201-6p6spc]
C505  0.1uF  [c201-6p6spc]
C1056  0.47uF  [c201-6p6spc]
C1057  4.7uF  [c402-25]
R1040  0  [r402-25]
sheet SH23 - DDR3 EMIF1 TESTPOINTS
TP1MC1  TP_VIA_MEM2  [tp1-18rd8]
TP1MC2  TP_VIA_MEM2  [tp1-18rd8]
TP1MC3  TP_VIA_MEM2  [tp1-18rd8]
TP1MC4  TP_VIA_MEM2  [tp1-18rd8]
TP1MC5  TP_VIA_MEM2  [tp1-18rd8]
TP1MC6  TP_VIA_MEM2  [tp1-18rd8]
TP1MC7  TP_VIA_MEM2  [tp1-18rd8]
TP1MC8  TP_VIA_MEM2  [tp1-18rd8]
TP1MC9  TP_VIA_MEM2  [tp1-18rd8]
TP1MC10  TP_VIA_MEM2  [tp1-18rd8]
TP1MC11  TP_VIA_MEM2  [tp1-18rd8]
TP1MC12  TP_VIA_MEM2  [tp1-18rd8]
TP1MC13  TP_VIA_MEM2  [tp1-18rd8]
TP1MC14  TP_VIA_MEM2  [tp1-18rd8]
TP1MC15  TP_VIA_MEM2  [tp1-18rd8]
TP1MC16  TP_VIA_MEM2  [tp1-18rd8]
TP1MC17  TP_VIA_MEM2  [tp1-18rd8]
TP1MC18  TP_VIA_MEM2  [tp1-18rd8]
TP1MC19  TP_VIA_MEM2  [tp1-18rd8]
TP1MC20  TP_VIA_MEM2  [tp1-18rd8]
TP1MC21  TP_VIA_MEM2  [tp1-18rd8]
TP1MC22  TP_VIA_MEM2  [tp1-18rd8]
TP1MC23  TP_VIA_MEM2  [tp1-18rd8]
TP1MC24  TP_VIA_MEM2  [tp1-18rd8]
TP1MC25  TP_VIA_MEM2  [tp1-18rd8]
TP1MC26  TP_VIA_MEM2  [tp1-18rd8]
TP1MC28  TP_VIA_MEM2  [tp1-rd8]
TP1MC29  TP_VIA_MEM2  [tp1-rd8]
TP2MA1  TP_VIA_MEM0  [tp1-18rd8]
TP2MA2  TP_VIA_MEM0  [tp1-18rd8]
TP2MA3  TP_VIA_MEM0  [tp1-18rd8]
TP2MA4  TP_VIA_MEM0  [tp1-18rd8]
TP2MA5  TP_VIA_MEM0  [tp1-18rd8]
TP2MA6  TP_VIA_MEM0  [tp1-18rd8]
TP2MA7  TP_VIA_MEM0  [tp1-18rd8]
TP2MA8  TP_VIA_MEM0  [tp1-18rd8]
TP2MA9  TP_VIA_MEM0  [tp1-18rd8]
TP2MA10  TP_VIA_MEM0  [tp1-18rd8]
TP2MA11  TP_VIA_MEM0  [tp1-18rd8]
TP2MA12  TP_VIA_MEM0  [tp1-18rd8]
TP2MA13  TP_VIA_MEM0  [tp1-18rd8]
TP2MA14  TP_VIA_MEM0  [tp1-18rd8]
TP2MA15  TP_VIA_MEM0  [tp1-18rd8]
TP2MA16  TP_VIA_MEM0  [tp1-18rd8]
TP2MA17  TP_VIA_MEM0  [tp1-18rd8]
TP2MA18  TP_VIA_MEM0  [tp1-18rd8]
TP2MA19  TP_VIA_MEM0  [tp1-18rd8]
TP2MA20  TP_VIA_MEM0  [tp1-18rd8]
TP2MA21  TP_VIA_MEM0  [tp1-18rd8]
TP2MA22  TP_VIA_MEM0  [tp1-18rd8]
TP2MA23  TP_VIA_MEM0  [tp1-18rd8]
TP2MA24  TP_VIA_MEM0  [tp1-18rd8]
TP2MA25  TP_VIA_MEM0  [tp1-18rd8]
TP2MA26  TP_VIA_MEM0  [tp1-18rd8]
TP2MA27  TP_VIA_MEM0  [tp1-18rd8]
TP2MA28  TP_VIA_MEM0  [tp1-rd8]
TP2MA29  TP_VIA_MEM0  [tp1-rd8]
TP2MB1  TP_VIA_MEM1  [tp1-18rd8]
TP2MB2  TP_VIA_MEM1  [tp1-18rd8]
TP2MB3  TP_VIA_MEM1  [tp1-18rd8]
TP2MB4  TP_VIA_MEM1  [tp1-18rd8]
TP2MB5  TP_VIA_MEM1  [tp1-18rd8]
TP2MB6  TP_VIA_MEM1  [tp1-18rd8]
TP2MB7  TP_VIA_MEM1  [tp1-18rd8]
TP2MB8  TP_VIA_MEM1  [tp1-18rd8]
TP2MB9  TP_VIA_MEM1  [tp1-18rd8]
TP2MB10  TP_VIA_MEM1  [tp1-18rd8]
TP2MB11  TP_VIA_MEM1  [tp1-18rd8]
TP2MB12  TP_VIA_MEM1  [tp1-18rd8]
TP2MB13  TP_VIA_MEM1  [tp1-18rd8]
TP2MB14  TP_VIA_MEM1  [tp1-18rd8]
TP2MB15  TP_VIA_MEM1  [tp1-18rd8]
TP2MB16  TP_VIA_MEM1  [tp1-18rd8]
TP2MB17  TP_VIA_MEM1  [tp1-18rd8]
TP2MB18  TP_VIA_MEM1  [tp1-18rd8]
TP2MB19  TP_VIA_MEM1  [tp1-18rd8]
TP2MB20  TP_VIA_MEM1  [tp1-18rd8]
TP2MB21  TP_VIA_MEM1  [tp1-18rd8]
TP2MB22  TP_VIA_MEM1  [tp1-18rd8]
TP2MB23  TP_VIA_MEM1  [tp1-18rd8]
TP2MB24  TP_VIA_MEM1  [tp1-18rd8]
TP2MB25  TP_VIA_MEM1  [tp1-18rd8]
TP2MB26  TP_VIA_MEM1  [tp1-18rd8]
TP2MB27  TP_VIA_MEM1  [tp1-18rd8]
TP2MB28  TP_VIA_MEM1  [tp1-rd8]
TP2MB29  TP_VIA_MEM1  [tp1-rd8]
TP2MC1  TP_VIA_MEM2  [tp1-18rd8]
sheet SH24 - DDR3  BANK 1 ECC
C205  0.22uF  [c201-6p6spc]
C617  0.22uF  [c201-6p6spc]
R693  240  [r402-25]
R1087  240  [r402-25]
U67  MT41K512M8RH-125-AAT:E  (IT)  [bga6x13-p8-tna-pkg]
sheet SH25 - DDR3 MEMORY BANK 1
C177  0.22uF  [c201-6p6spc]
C178  0.22uF  [c201-6p6spc]
C197  0.22uF  [c201-6p6spc]
C198  0.22uF  [c201-6p6spc]
C628  0.22uF  [c201-6p6spc]
C629  0.22uF  [c201-6p6spc]
C651  0.22uF  [c201-6p6spc]
C652  0.22uF  [c201-6p6spc]
R288  240  [r402-25]
R289  240  [r402-25]
R694  240  [r402-25]
R695  240  [r402-25]
R1088  240  [r402-25]
R1089  240  [r402-25]
R1090  240  [r402-25]
R1091  240  [r402-25]
U68  MT41K512M8RH-125-AAT:E  (IT)  [bga6x13-p8-tna-pkg]
U69  MT41K512M8RH-125-AAT:E  (IT)  [bga6x13-p8-tna-pkg]
U115  MT41K512M8RH-125-AAT:E  (IT)  [bga6x13-p8-tna-pkg]
U116  MT41K512M8RH-125-AAT:E  (IT)  [bga6x13-p8-tna-pkg]
sheet SH26 - DDR3 MEMORY CAPS BANK 1
C158  0.22uF  [c201-6p6spc]
C159  0.22uF  [c201-6p6spc]
C160  0.22uF  [c201-6p6spc]
C161  0.22uF  [c201-6p6spc]
C162  0.22uF  [c201-6p6spc]
C163  0.22uF  [c201-6p6spc]
C169  0.22uF  [c201-6p6spc]
C170  0.22uF  [c201-6p6spc]
C171  0.22uF  [c201-6p6spc]
C172  0.22uF  [c201-6p6spc]
C184  0.22uF  [c201-6p6spc]
C185  0.22uF  [c201-6p6spc]
C189  0.22uF  [c201-6p6spc]
C190  0.22uF  [c201-6p6spc]
C195  0.22uF  [c201-6p6spc]
C196  0.22uF  [c201-6p6spc]
C199  0.22uF  [c201-6p6spc]
C200  0.22uF  [c201-6p6spc]
C214  10uF  [c603-35x45]
C581  0.22uF  [c201-6p6spc]
C582  0.22uF  [c201-6p6spc]
C585  0.22uF  [c201-6p6spc]
C586  0.22uF  [c201-6p6spc]
C590  0.22uF  [c201-6p6spc]
C591  0.22uF  [c201-6p6spc]
C592  0.22uF  [c201-6p6spc]
C593  0.22uF  [c201-6p6spc]
C595  0.22uF  [c201-6p6spc]
C596  0.22uF  [c201-6p6spc]
C602  0.22uF  [c201-6p6spc]
C603  0.22uF  [c201-6p6spc]
C608  0.22uF  [c201-6p6spc]
C609  0.22uF  [c201-6p6spc]
C614  0.22uF  [c201-6p6spc]
C615  0.22uF  [c201-6p6spc]
C616  0.22uF  [c201-6p6spc]
C625  0.22uF  [c201-6p6spc]
C630  0.22uF  [c201-6p6spc]
C631  0.22uF  [c201-6p6spc]
C632  0.22uF  [c201-6p6spc]
C633  0.22uF  [c201-6p6spc]
C636  0.22uF  [c201-6p6spc]
C637  0.22uF  [c201-6p6spc]
C640  0.22uF  [c201-6p6spc]
C641  0.22uF  [c201-6p6spc]
C644  0.22uF  [c201-6p6spc]
C645  0.22uF  [c201-6p6spc]
C649  0.22uF  [c201-6p6spc]
C650  0.22uF  [c201-6p6spc]
C664  0.22uF  [c201-6p6spc]
C665  10uF  [c603-35x45]
C666  0.22uF  [c201-6p6spc]
C667  0.22uF  [c201-6p6spc]
C668  0.22uF  [c201-6p6spc]
C669  0.22uF  [c201-6p6spc]
C670  10uF  [c603-35x45]
C671  0.22uF  [c201-6p6spc]
C672  0.22uF  [c201-6p6spc]
C673  10uF  [c603-35x45]
C674  0.22uF  [c201-6p6spc]
C675  0.22uF  [c201-6p6spc]
C676  0.22uF  [c201-6p6spc]
C677  0.22uF  [c201-6p6spc]
C678  10uF  [c603-35x45]
C679  0.22uF  [c201-6p6spc]

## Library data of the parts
C106 C113 = Cap_18pF_Cermc_50V_5%_603_0: Part #: 101782-1334R
C110 C117 C143 C148 C485 C508 C521 C522 C552 C555 C559 C563 C570 C574 C578 = CAP: Part #: 103241-1100R
C123 C124 C126 C128 = CAP_NP_3: Part #: 102756-1184R
C145 = CAP_NP_1: Part #: 101587-1100R
C146 C573 = CAP: Part #: 101587-1100R
C550 C553 = CAP: Part #: 103367-1102R
C551 C554 = CAP: Part #: 103241-1101R
R204 = R: Part #: R0201-NOPOP
R216 R269 R670 = R: Part #: 103158-0001R
R256 = R: Part #: 102145-2002R
R620 = R: Part #: 103158-1003R
R632 = R: Part #: 103158-1002R
R795 R800 R1038 R1040 = R: Part #: 101370-0001R
R796 = R: Part #: R0402-NOPOP
TP55 TP58-TP60 = TESTPOINT: Part #: TP-30RD13-NO-POP
U60-U62 = 1G08: Part #: 101057-0008R
Y3 = CRYSTAL_0: Part #: 102883-0032R
Y5 = CRYSTAL_22.5792MHz: Part #: 102740-0225R
Y6 = CRYSTAL_0_v2: Part #: 101590-0200R
C462 C468 C477 C480 C481 C501 C504 C509 C512 C516 C517 C520 C529 C1054 C1055 = CAP_NP: Part #: 102962-0100R
C104 C214 C355 C357 C382 C406 C436 C493 C665 C670 C673 C678 = CAP: Part #: 102963-0101R
C363 C364 C368 C370 C386 C388 C390-C392 C399 C400 C412 C414 C415 C437 C444 C450 C455 C458 C461 C498 C507 C518 C542 C1053 = NPCap_0: Part #: 103241-1100R
C89 C107 C109 C112 C118 C119 C127 C365 C366 C369 C371 C372 C384 C385 C387 C389 C396-C398 C401 C402 C438 C442 C443 C445 C449 C454 C457 C463 C464 C466 C467 C469 C471 C473-C475 C482 C484 C492 C494-C496 C500 C502 C505 C524 C526 C530 C545 C699 C700 = CAP_NP: Part #: 103241-1100R
R799 = R: Part #: r0402-nopop
R801 = R: Part #: 101370-1502R
U52 = J6ECO_RevC_0: Part #: 104492-0002R-TI
U136 = tps2115a: Part #: 104415-0001R
TP51 = TestPoint1_0: Part #: TP-18RD8-NO-POP
C140 C356 = CAP: Part #: 103911-0221R
C158 C560 C561 C564 C571 C609 = CAP: Part #: 103214-1220R
C569 C576 = CAP: Part #: 102962-0100R
C572 C577 = CAP: Part #: 103649-0470R
C413 C420 C422 C491 C1052 = CAP_NP_0: Part #: 103241-1101R
C418 C426 C429 C490 C1051 = CAP_NP_0: Part #: 103214-0100R
C419 C425 C427 C497 C1050 = CAP_NP_0: Part #: 103367-1102R
E3-E6 E10 = NFM_1: Part #: 102569-1470R
C90 C92 C96 C395 C465 = NPCap_0: Part #: 103214-1220R
C91 C95 C111 C367 C373 C393 C483 = NPCap_0: Part #: 103214-0100R
C93 C94 C108 C374 C394 C478 C1056 = NPCap_0: Part #: 104275-1470R
C105 C359 C361 C456 = NPCap_0: Part #: 103649-0220R
C360 C362 C452 C453 C487 C1057 = NPCap_0: Part #: 103649-0470R
C460 = CAP: Part #: 104300-0101R
TP1MC1-TP1MC26 TP2MC1 = TP_VIA_MEM2_0: Part #: TP-18RD8-NO-POP
TP1MC28 TP1MC29 = TP_VIA_MEM2_0: Part #: no-pop
TP2MA1-TP2MA27 = TP_VIA_MEM0_0: Part #: TP-18RD8-NO-POP
TP2MA28 TP2MA29 = TP_VIA_MEM0_0: Part #: no-pop
TP2MB1-TP2MB27 = TP_VIA_MEM1_0: Part #: TP-18RD8-NO-POP
TP2MB28 TP2MB29 = TP_VIA_MEM1_0: Part #: no-pop
C159-C163 C169-C172 C177 C178 C184 C185 C189 C190 C195-C200 C205 C581 C582 C585 C586 C590 C592 C593 C595 C596 C608 C615-C617 C628-C631 C636 C637 C644 C645 C649-C652 C664 C666-C669 C671 C672 C674-C677 C679 = CAP_NP_0: Part #: 103214-1220R
R288 R289 R693-R695 R1087-R1091 = R: Part #: 102145-2401R
U67-U69 U115 U116 = EDJ1108DBSE_0: Part #: 104695-0125R
C591 C602 C603 C614 C625 C632 C633 C640 C641 = CAP_NP_0: Part #: 103214-1220R; SD PCB Footprint: EIA0402

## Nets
GND: C89.2 C90.1 C91.1 C92.1 C93.1 C94.1 C95.1 C96.1 C104.2 C105.1 C106.2 C107.2 C108.1 C109.2 C110.2 C111.1 C112.2 C113.2 C117.2 C118.2 C119.2 C127.2 C140.2 C143.2 C145.2 C146.2 C148.2 C158.2 C159.2 C160.2 C161.2 C162.2 C163.2 C169.2 C170.2 C171.2 C172.2 C177.2 C178.2 C184.2 C185.2 C189.2 C190.2 C195.2 C196.2 C199.2 C200.2 C214.2 C355.2 C356.2 C357.2 C359.1 C360.1 C361.1 C362.1 C363.1 C364.1 C365.2 C366.2 C367.1 C368.1 C369.2 C370.1 C371.2 C372.2 C373.1 C374.1 C382.2 C384.2 C385.2 C386.1 C387.2 C388.1 C389.2 C390.1 C391.1 C392.1 C393.1 C394.1 C395.1 C396.2 C397.2 C398.2 C399.1 C400.1 C401.2 C402.2 C406.2 C412.1 C413.2 C414.1 C415.1 C418.2 C419.2 C420.2 C422.2 C425.2 C426.2 C427.2 C429.2 C436.2 C437.1 C438.2 C442.2 C443.2 C444.1 C445.2 C449.2 C450.1 C452.1 C453.1 C454.2 C455.1 C456.1 C457.2 C458.1 C460.2 C461.1 C462.2 C463.2 C464.2 C465.1 C466.2 C467.2 C468.2 C469.2 C471.2 C473.2 C474.2 C475.2 C477.2 C478.1 C480.2 C481.2 C482.2 C483.1 C484.2 C485.2 C487.1 C490.2 C491.2 C492.2 C493.2 C494.2 C495.2 C496.2 C497.2 C498.1 C500.2 C501.2 C502.2 C504.2 C505.2 C507.1 C508.2 C509.2 C512.2 C516.2 C517.2 C518.1 C520.2 C521.2 C522.2 C524.2 C526.2 C529.2 C530.2 C542.1 C545.2 C550.2 C551.2 C552.2 C553.2 C554.2 C555.2 C559.2 C560.2 C561.2 C563.2 C564.2 C569.2 C570.2 C571.2 C572.2 C573.2 C574.2 C576.2 C577.2 C578.2 C581.2 C582.2 C585.2 C586.2 C590.2 C591.2 C592.2 C593.2 C595.2 C596.2 C602.2 C603.2 C608.2 C609.2 C614.2 C615.2 C616.2 C617.2 C625.2 C628.2 C629.2 C630.2 C631.2 C632.2 C633.2 C636.2 C637.2 C640.2 C641.2 C644.2 C645.2 C649.2 C650.2 C664.2 C665.2 C666.2 C667.2 C668.2 C669.2 C670.2 C671.2 C672.2 C673.2 C674.2 C675.2 C676.2 C677.2 C678.2 C679.2 C699.2 C700.2 C1050.2 C1051.2 C1052.2 C1053.1 C1054.2 C1055.2 C1056.1 C1057.1 E3.2 E4.2 E5.2 E6.2 E10.2 R256.1 R288.2 R289.2 R620.2 R693.2 R694.2 R695.2 R801.1 R1087.2 R1088.2 R1089.2 R1090.2 R1091.2 U52.A1(VSS.9) U52.A2(VSS.11) U52.A6(VSS.15) U52.A14(VSS.41) U52.A23(VSS.68) U52.A28(VSS.79) U52.AA8(VSS.17) U52.AA9(VSS.19) U52.AA10(VSSA_CSI.1) U52.AA14(VSS.48) U52.AA15(VSS.51) U52.AA20(VSS.61) U52.AB14(VSS.40) U52.AB20(VSS.60) U52.AD1(VSS.3) U52.AD24(VSS.70) U52.AG1(VSS.2) U52.AH1(VSS.1) U52.AH2(VSS.10) U52.AH8(VSSA_CSI.2) U52.AH20(VSS.52) U52.AH28(VSS.75) U52.B1(VSS.8) U52.D13(VSS.39) U52.D19(VSS.59) U52.E13(VSS.38) U52.E19(VSS.58) U52.F1(VSS.7) U52.F7(VSS.54) U52.G7(VSS.57) U52.G8(VSS.65) U52.G9(VSS.66) U52.H12(VSS.33) U52.J12(VSS.32) U52.J15(VSS.XX) U52.J28(VSS.78) U52.K1(VSS.6) U52.K4(VSS.12) U52.K5(VSS.13) U52.K15(VSS.28) U52.K24(VSS.55) U52.K25(VSS.56) U52.L13(VSS.37) U52.L14(VSS.46) U52.M19(VSS.69) U52.N14(VSS.X5) U52.N15(VSS.16) U52.N19(VSS.18) U52.N24(VSS.72) U52.N25(VSS.74) U52.P28(VSS.77) U52.R1(VSS.5) U52.R12(VSS.29) U52.R13(VSS.X6) U52.R15(VSSA_VIDEO) U52.R21(VSS.64) U52.T10(VSS.21) U52.T11(VSS.26) U52.T12(VSS.23) U52.T14(VSS.X7) U52.T15(VSS.42) U52.T17(VSS.47) U52.T18(VSS.24) U52.T21(VSS.27) U52.U14(VSS) U52.U15(VSS.X8) U52.U17(VSS.X9) U52.U20(VSS.62) U52.U21(VSS.63) U52.V15(VSS.30) U52.V17(VSS.X10) U52.W1(VSS.4) U52.W15(VSS.36) U52.W24(VSS.71) U52.W25(VSS.73) U52.W28(VSS.76) U60.3(GND) U61.3(GND) U62.3(GND) U67.A1(VSS.1) U67.A8(VSS.2) U67.B1(VSS.3) U67.B2(VSSQ) U67.B8(VSSQ) U67.C9(VSSQ) U67.D1(VSSQ) U67.D8(VSS.4) U67.D9(VSSQ) U67.F2(VSS.5) U67.F8(VSS.6) U67.J1(VSS.7) U67.J9(VSS.8) U67.L1(VSS.9) U67.L9(VSS.10) U67.N1(VSS.11) U67.N9(VSS.12) U68.A1(VSS.1) U68.A8(VSS.2) U68.B1(VSS.3) U68.B2(VSSQ) U68.B8(VSSQ) U68.C9(VSSQ) U68.D1(VSSQ) U68.D8(VSS.4) U68.D9(VSSQ) U68.F2(VSS.5) U68.F8(VSS.6) U68.J1(VSS.7) U68.J9(VSS.8) U68.L1(VSS.9) U68.L9(VSS.10) U68.N1(VSS.11) U68.N9(VSS.12) U69.A1(VSS.1) U69.A8(VSS.2) U69.B1(VSS.3) U69.B2(VSSQ) U69.B8(VSSQ) U69.C9(VSSQ) U69.D1(VSSQ) U69.D8(VSS.4) U69.D9(VSSQ) U69.F2(VSS.5) U69.F8(VSS.6) U69.J1(VSS.7) U69.J9(VSS.8) U69.L1(VSS.9) U69.L9(VSS.10) U69.N1(VSS.11) U69.N9(VSS.12) U115.A1(VSS.1) U115.A8(VSS.2) U115.B1(VSS.3) U115.B2(VSSQ) U115.B8(VSSQ) U115.C9(VSSQ) U115.D1(VSSQ) U115.D8(VSS.4) U115.D9(VSSQ) U115.F2(VSS.5) U115.F8(VSS.6) U115.J1(VSS.7) U115.J9(VSS.8) U115.L1(VSS.9) U115.L9(VSS.10) U115.N1(VSS.11) U115.N9(VSS.12) U116.A1(VSS.1) U116.A8(VSS.2) U116.B1(VSS.3) U116.B2(VSSQ) U116.B8(VSSQ) U116.C9(VSSQ) U116.D1(VSSQ) U116.D8(VSS.4) U116.D9(VSSQ) U116.F2(VSS.5) U116.F8(VSS.6) U116.J1(VSS.7) U116.J9(VSS.8) U116.L1(VSS.9) U116.L9(VSS.10) U116.N1(VSS.11) U116.N9(VSS.12) U136.2(D0) U136.5(GND) U136.PAD Y3.2 Y3.3 ; also on sheet 3 5 7 10 23 24 25 26 27 28 29 30 31 32 33 34 35 36 37 38 39 40 41 42 43 44 45 46 47 48 49 50 51 52 53 54 55 56 57 58 59 62 63 64 65 66 67 68 69 70 71
VDDSHV11: C458.2 R799.1 U52.J8(VDDSHV11.2) U52.K8(VDDSHV11.1) U136.7(OUT)
APP_BD_PORz: R670.2 ; also on sheet 50
CAP_VBBLDO_DSP: C477.1 U52.K9(CAP_VBBLDO_DSP)
CAP_VBBLDO_GPU: C501.1 U52.Y14(CAP_VBBLDO_GPU)
CAP_VBBLDO_IVA1: C481.1 U52.J10(CAP_VBBLDO_IVA1)
CAP_VBBLDO_MPU: C509.1 U52.J16(CAP_VBBLDO_MPU)
CAP_VDDRAM_CORE1: C529.1 U52.T20(CAP_VDDRAM_CORE1)
CAP_VDDRAM_CORE3: C468.1 U52.L9(CAP_VDDRAM_CORE3)
CAP_VDDRAM_CORE4: C517.1 U52.J19(CAP_VDDRAM_CORE4)
CAP_VDDRAM_DSP: C462.1 U52.J9(CAP_VDDRAM_DSP)
CAP_VDDRAM_GPU: C480.1 U52.Y13(CAP_VDDRAM_GPU)
CAP_VDDRAM_IVA: C504.1 U52.K16(CAP_VDDRAM_IVA)
CAP_VDDRAM_MPU2: C520.1 U52.K19(CAP_VDDRAM_MPU2)
CORE_VDD: C117.1 C363.2 C364.2 C386.2 C388.2 C390.2 C393.2 C394.2 C395.2 C456.2 C487.2 C498.2 U52.AB15(VDD_RTC) U52.H13(VDD.18) U52.H14(VDD.22) U52.J17(VDD.X1) U52.J18(VDD.X2) U52.L7(VDD.34) U52.L8(VDD.15) U52.N10(VDD.6) U52.N13(VDD.16) U52.P11(VDD.9) U52.P12(VDD.12) U52.P13(VDD.X3) U52.R11(VDD.8) U52.R16(VDD.26) U52.R19(VDD.27) U52.T13(VDD.13) U52.T16(VDD.25) U52.T19(VDD.X7) U52.U8(VDD.29) U52.U9(VDD.2) U52.U13(VDD.3) U52.U16(VDD.X8) U52.V8(VDD.1) U52.V16(VDD.X9) ; also on sheet 56 57 59
CPU_NMIn: R632.2 U52.D21(NMIN)
CPU_POR_RESETn: U52.AB17(RTC_PORZ) U62.2(A) ; also on sheet 52
CPU_RESETn: U60.1(B) ; also on sheet 52
CPU_VDD_DDR: C140.1 C143.1 C148.1 C508.1 C559.1 C560.1 C561.1 C563.1 C564.1 C569.1 C570.1 C571.1 C572.1 C574.1 C576.1 C577.1 C578.1 R1038.2 U52.AA21(VDDS_DDR1.4) U52.AA22(VDDS_DDR1.2) U52.AB21(VDDS_DDR1.3) U52.AB22(VDDS_DDR1.7) U52.AB24(VDDS_DDR1.10) U52.AB25(VDDS_DDR1.11) U52.AC22(VDDS_DDR1.6) U52.AD26(VDDS_DDR1.12) U52.AG20(VDDS_DDR1.9) U52.AG28(VDDS_DDR1.5) U52.AH27(VDDS_DDR1.13) U52.T24(VDDS_DDR1.14) U52.T25(VDDS_DDR1.15) U52.W16(VDDS_DDR1.1) U52.W27(VDDS_DDR1.8) ; also on sheet 5 55
DCAN1_RX: U52.AD17(WAKEUP0/dcan1_rx/gpio1_0/sys_nirq2) ; also on sheet 41
DDR1_A0: TP1MC14.1 TP2MA15.1 TP2MB15.1 U67.K3(A0) U68.K3(A0) U69.K3(A0) U115.K3(A0) U116.K3(A0) ; also on sheet 5 23
DDR1_A1: TP1MC16.1 TP2MA19.1 TP2MB19.1 U67.L7(A1) U68.L7(A1) U69.L7(A1) U115.L7(A1) U116.L7(A1) ; also on sheet 5 23
DDR1_A2: TP1MC26.1 TP2MA20.1 TP2MB20.1 U67.L3(A2) U68.L3(A2) U69.L3(A2) U115.L3(A2) U116.L3(A2) ; also on sheet 5 23
DDR1_A3: TP1MC13.1 TP2MA14.1 TP2MB14.1 U67.K2(A3) U68.K2(A3) U69.K2(A3) U115.K2(A3) U116.K2(A3) ; also on sheet 5 23
DDR1_A4: TP1MC17.1 TP2MA17.1 TP2MB17.1 U67.L8(A4) U68.L8(A4) U69.L8(A4) U115.L8(A4) U116.L8(A4) ; also on sheet 5 23
DDR1_A5: TP1MC18.1 TP2MA18.1 TP2MB18.1 U67.L2(A5) U68.L2(A5) U69.L2(A5) U115.L2(A5) U116.L2(A5) ; also on sheet 5 23
DDR1_A6: TP1MC21.1 TP2MA24.1 TP2MB24.1 U67.M8(A6) U68.M8(A6) U69.M8(A6) U115.M8(A6) U116.M8(A6) ; also on sheet 5 23
DDR1_A7: TP1MC22.1 TP2MA23.1 TP2MB23.1 U67.M2(A7) U68.M2(A7) U69.M2(A7) U115.M2(A7) U116.M2(A7) ; also on sheet 5 23
DDR1_A8: TP1MC25.1 TP2MA27.1 TP2MB27.1 U67.N8(A8) U68.N8(A8) U69.N8(A8) U115.N8(A8) U116.N8(A8) ; also on sheet 5 23
DDR1_A9: TP1MC19.1 TP2MA21.1 TP2MB21.1 U67.M3(A9) U68.M3(A9) U69.M3(A9) U115.M3(A9) U116.M3(A9) ; also on sheet 5 23
DDR1_A10: TP1MC6.1 TP2MA7.1 TP2MB7.1 U67.H7(A10/AP) U68.H7(A10/AP) U69.H7(A10/AP) U115.H7(A10/AP) U116.H7(A10/AP) ; also on sheet 5 23
DDR1_A11: TP1MC20.1 TP2MA22.1 TP2MB22.1 U67.M7(A11) U68.M7(A11) U69.M7(A11) U115.M7(A11) U116.M7(A11) ; also on sheet 5 23
DDR1_A12: TP1MC15.1 TP2MA16.1 TP2MB16.1 U67.K7(A12/~{BC}) U68.K7(A12/~{BC}) U69.K7(A12/~{BC}) U115.K7(A12/~{BC}) U116.K7(A12/~{BC}) ; also on sheet 5 23
DDR1_A13: TP1MC23.1 TP2MA26.1 TP2MB26.1 U67.N3(A13) U68.N3(A13) U69.N3(A13) U115.N3(A13) U116.N3(A13) ; also on sheet 5 23
DDR1_A14: TP1MC24.1 TP2MA25.1 TP2MB25.1 U67.N7(A14/NC) U68.N7(A14/NC) U69.N7(A14/NC) U115.N7(A14/NC) U116.N7(A14/NC) ; also on sheet 5 23
DDR1_A15: TP1MC9.1 TP2MA12.1 TP2MB12.1 U67.J7(A15/NC) U68.J7(A15/NC) U69.J7(A15/NC) U115.J7(A15/NC) U116.J7(A15/NC) ; also on sheet 5 23
DDR1_BA0: TP1MC10.1 TP2MA10.1 TP2MB10.1 U67.J2(BA0) U68.J2(BA0) U69.J2(BA0) U115.J2(BA0) U116.J2(BA0) ; also on sheet 5 23
DDR1_BA1: TP1MC12.1 TP2MA13.1 TP2MB13.1 U67.K8(BA1) U68.K8(BA1) U69.K8(BA1) U115.K8(BA1) U116.K8(BA1) ; also on sheet 5 23
DDR1_BA2: TP1MC11.1 TP2MA11.1 TP2MB11.1 U67.J3(BA2) U68.J3(BA2) U69.J3(BA2) U115.J3(BA2) U116.J3(BA2) ; also on sheet 5 23
DDR1_CASN: TP1MC5.1 TP2MA6.1 TP2MB6.1 U67.G3(~{CAS}) U68.G3(~{CAS}) U69.G3(~{CAS}) U115.G3(~{CAS}) U116.G3(~{CAS}) ; also on sheet 5 23
DDR1_CKE: TP1MC3.1 TP2MA1.1 TP2MB1.1 U67.F9(CKE1) U67.G9(CKE) U68.F9(CKE1) U68.G9(CKE) U69.F9(CKE1) U69.G9(CKE) U115.F9(CKE1) U115.G9(CKE) U116.F9(CKE1) U116.G9(CKE) ; also on sheet 5 23
DDR1_CLK0: TP1MC2.1 TP2MA4.1 TP2MB4.1 U67.F7(CK) U68.F7(CK) U69.F7(CK) U115.F7(CK) U116.F7(CK) ; also on sheet 5 23
DDR1_CLK0N: TP1MC4.1 TP2MA5.1 TP2MB5.1 U67.G7(~{CK}) U68.G7(~{CK}) U69.G7(~{CK}) U115.G7(~{CK}) U116.G7(~{CK}) ; also on sheet 5 23
DDR1_CSN0: TP1MC8.1 TP2MA8.1 TP2MB8.1 U67.H2(~{CS}) U68.H2(~{CS}) U69.H2(~{CS}) U115.H2(~{CS}) U116.H2(~{CS}) ; also on sheet 5 23
DDR1_CSN1: TP1MC29.1 TP2MA29.1 TP2MB29.1 U67.H1(~{CS1}) U68.H1(~{CS1}) U69.H1(~{CS1}) U115.H1(~{CS1}) U116.H1(~{CS1}) ; also on sheet 5 23
DDR1_D0: U115.E7(DQ7) ; also on sheet 5
DDR1_D1: U115.D2(DQ6) ; also on sheet 5
DDR1_D2: U115.C8(DQ3) ; also on sheet 5
DDR1_D3: U115.E8(DQ5) ; also on sheet 5
DDR1_D4: U115.C7(DQ1) ; also on sheet 5
DDR1_D5: U115.E3(DQ4) ; also on sheet 5
DDR1_D6: U115.C2(DQ2) ; also on sheet 5
DDR1_D7: U115.B3(DQ0) ; also on sheet 5
DDR1_D8: U69.E3(DQ4) ; also on sheet 5
DDR1_D9: U69.E7(DQ7) ; also on sheet 5
DDR1_D10: U69.E8(DQ5) ; also on sheet 5
DDR1_D11: U69.C7(DQ1) ; also on sheet 5
DDR1_D12: U69.C8(DQ3) ; also on sheet 5
DDR1_D13: U69.B3(DQ0) ; also on sheet 5
DDR1_D14: U69.C2(DQ2) ; also on sheet 5
DDR1_D15: U69.D2(DQ6) ; also on sheet 5
DDR1_D16: U116.C7(DQ1) ; also on sheet 5
DDR1_D17: U116.C2(DQ2) ; also on sheet 5
DDR1_D18: U116.B3(DQ0) ; also on sheet 5
DDR1_D19: U116.C8(DQ3) ; also on sheet 5
DDR1_D20: U116.E8(DQ5) ; also on sheet 5
DDR1_D21: U116.E7(DQ7) ; also on sheet 5
DDR1_D22: U116.E3(DQ4) ; also on sheet 5
DDR1_D23: U116.D2(DQ6) ; also on sheet 5
DDR1_D24: U68.C7(DQ1) ; also on sheet 5
DDR1_D25: U68.E8(DQ5) ; also on sheet 5
DDR1_D26: U68.C8(DQ3) ; also on sheet 5
DDR1_D27: U68.E3(DQ4) ; also on sheet 5
DDR1_D28: U68.E7(DQ7) ; also on sheet 5
DDR1_D29: U68.D2(DQ6) ; also on sheet 5
DDR1_D30: U68.B3(DQ0) ; also on sheet 5
DDR1_D31: U68.C2(DQ2) ; also on sheet 5
DDR1_DQM0: U115.B7(DM/TDQS) ; also on sheet 5
DDR1_DQM1: U69.B7(DM/TDQS) ; also on sheet 5
DDR1_DQM2: U116.B7(DM/TDQS) ; also on sheet 5
DDR1_DQM3: U68.B7(DM/TDQS) ; also on sheet 5
DDR1_DQM_ECC: U67.B7(DM/TDQS) ; also on sheet 5
DDR1_DQS0: U115.C3(DQS) ; also on sheet 5
DDR1_DQS1: U69.C3(DQS) ; also on sheet 5
DDR1_DQS2: U116.C3(DQS) ; also on sheet 5
DDR1_DQS3: U68.C3(DQS) ; also on sheet 5
DDR1_DQS_ECC: U67.C3(DQS) ; also on sheet 5
DDR1_DQSN0: U115.D3(~{DQS}) ; also on sheet 5
DDR1_DQSN1: U69.D3(~{DQS}) ; also on sheet 5
DDR1_DQSN2: U116.D3(~{DQS}) ; also on sheet 5
DDR1_DQSN3: U68.D3(~{DQS}) ; also on sheet 5
DDR1_DQSN_ECC: U67.D3(~{DQS}) ; also on sheet 5
DDR1_ECC_D0: U67.E8(DQ5) ; also on sheet 5
DDR1_ECC_D1: U67.C8(DQ3) ; also on sheet 5
DDR1_ECC_D2: U67.E3(DQ4) ; also on sheet 5
DDR1_ECC_D3: U67.D2(DQ6) ; also on sheet 5
DDR1_ECC_D4: U67.C7(DQ1) ; also on sheet 5
DDR1_ECC_D5: U67.E7(DQ7) ; also on sheet 5
DDR1_ECC_D6: U67.C2(DQ2) ; also on sheet 5
DDR1_ECC_D7: U67.B3(DQ0) ; also on sheet 5
DDR1_ODT0: TP2MA3.1 TP2MB3.1 TP2MC1.1 U67.G1(ODT) U68.G1(ODT) U69.G1(ODT) U115.G1(ODT) U116.G1(ODT) ; also on sheet 5 23
DDR1_ODT1: TP1MC28.1 TP2MA28.1 TP2MB28.1 U67.F1(ODT1) U68.F1(ODT1) U69.F1(ODT1) U115.F1(ODT1) U116.F1(ODT1) ; also on sheet 5 23
DDR1_RASN: TP1MC1.1 TP2MA2.1 TP2MB2.1 U67.F3(~{RAS}) U68.F3(~{RAS}) U69.F3(~{RAS}) U115.F3(~{RAS}) U116.F3(~{RAS}) ; also on sheet 5 23
DDR1_RST: U67.N2(~{RESET}) U68.N2(~{RESET}) U69.N2(~{RESET}) U115.N2(~{RESET}) U116.N2(~{RESET}) ; also on sheet 23
DDR1_WEN: TP1MC7.1 TP2MA9.1 TP2MB9.1 U67.H3(~{WE}) U68.H3(~{WE}) U69.H3(~{WE}) U115.H3(~{WE}) U116.H3(~{WE}) ; also on sheet 5 23
DDR_VREFSTL1: C177.1 C178.1 C197.1 C198.1 C205.1 C617.1 C628.1 C629.1 C651.1 C652.1 U67.E1(VREFDQ) U67.J8(VREFCA) U68.E1(VREFDQ) U68.J8(VREFCA) U69.E1(VREFDQ) U69.J8(VREFCA) U115.E1(VREFDQ) U115.J8(VREFCA) U116.E1(VREFDQ) U116.J8(VREFCA) ; also on sheet 5 55
EMU_RSTn: U60.2(A) ; also on sheet 10
ENET_PORz: R795.2 R796.2 ; also on sheet 47 48
EVM_3V3: R632.1 ; also on sheet 3 4 10 24 25 26 27 28 29 30 31 32 33 34 35 36 37 38 39 40 42 43 44 45 46 47 48 49 50 51 55 56 58 59 62 63 65 66 67 69 70
EVM_VDD_DDR: C158.1 C159.1 C160.1 C161.1 C162.1 C163.1 C169.1 C170.1 C171.1 C172.1 C184.1 C185.1 C189.1 C190.1 C195.1 C196.1 C197.2 C198.2 C199.1 C200.1 C205.2 C214.1 C581.1 C582.1 C585.1 C586.1 C590.1 C591.1 C592.1 C593.1 C595.1 C596.1 C602.1 C603.1 C608.1 C609.1 C614.1 C615.1 C616.1 C625.1 C630.1 C631.1 C632.1 C633.1 C636.1 C637.1 C640.1 C641.1 C644.1 C645.1 C649.1 C650.1 C651.2 C652.2 C664.1 C665.1 C666.1 C667.1 C668.1 C669.1 C670.1 C671.1 C672.1 C673.1 C674.1 C675.1 C676.1 C677.1 C678.1 C679.1 U67.A2(VDD.1) U67.A9(VDD.2) U67.B9(VDDQ.1) U67.C1(VDDQ.2) U67.D7(VDD.3) U67.E2(VDDQ.3) U67.E9(VDDQ.4) U67.G2(VDD.4) U67.G8(VDD.5) U67.K1(VDD.6) U67.K9(VDD.7) U67.M1(VDD.8) U67.M9(VDD.9) U68.A2(VDD.1) U68.A9(VDD.2) U68.B9(VDDQ.1) U68.C1(VDDQ.2) U68.D7(VDD.3) U68.E2(VDDQ.3) U68.E9(VDDQ.4) U68.G2(VDD.4) U68.G8(VDD.5) U68.K1(VDD.6) U68.K9(VDD.7) U68.M1(VDD.8) U68.M9(VDD.9) U69.A2(VDD.1) U69.A9(VDD.2) U69.B9(VDDQ.1) U69.C1(VDDQ.2) U69.D7(VDD.3) U69.E2(VDDQ.3) U69.E9(VDDQ.4) U69.G2(VDD.4) U69.G8(VDD.5) U69.K1(VDD.6) U69.K9(VDD.7) U69.M1(VDD.8) U69.M9(VDD.9) U115.A2(VDD.1) U115.A9(VDD.2) U115.B9(VDDQ.1) U115.C1(VDDQ.2) U115.D7(VDD.3) U115.E2(VDDQ.3) U115.E9(VDDQ.4) U115.G2(VDD.4) U115.G8(VDD.5) U115.K1(VDD.6) U115.K9(VDD.7) U115.M1(VDD.8) U115.M9(VDD.9) U116.A2(VDD.1) U116.A9(VDD.2) U116.B9(VDDQ.1) U116.C1(VDDQ.2) U116.D7(VDD.3) U116.E2(VDDQ.3) U116.E9(VDDQ.4) U116.G2(VDD.4) U116.G8(VDD.5) U116.K1(VDD.6) U116.K9(VDD.7) U116.M1(VDD.8) U116.M9(VDD.9) ; also on sheet 23 55 56 57 59
IN2_VDDS18V: C699.1 R800.1 U136.6(IN2)
J6_VDD_1V8: C110.1 C357.1 C371.1 C382.1 C399.2 C400.2 C401.1 C402.1 C406.1 C461.2 C471.1 C518.2 C524.1 C530.1 R800.2 U52.AA18(VDDS18V_DDR1.1) U52.AA19(VDDS18V_DDR1.2) U52.AB13(VDDA_RTC) U52.G18(VDDS18V.8) U52.H17(VDDS18V.11) U52.J21(NC) U52.J22(NC) U52.M8(VDDS18V.9) U52.M9(VDDS18V.7) U52.N8(VDDS18V.4) U52.N21(VDDS18V_DDR1.6) U52.P8(VDDS18V.5) U52.P20(VDDS18V_DDR1.7) U52.P21(VDDS18V_DDR1.5) U52.R8(VDDS18V.3) U52.T8(VDDS18V.2) U52.V21(VDDS18V.12) U52.V22(VDDS18V.6) U52.W17(VDDS18V.10) U52.W18(VDDS18V.1) U52.W21(VDDS18V_DDR1.4) U52.Y21(VDDS18V_DDR1.3) ; also on sheet 3 56 57 59
J6_VDD_GPU: C89.1 C90.2 C105.2 C107.1 C108.2 C109.1 C111.2 C118.1 C119.1 C127.1 C361.2 C362.2 C372.1 C373.2 C374.2 C397.1 C398.1 C452.2 C453.2 C460.1 C463.1 C465.2 C469.1 C473.1 C475.1 C478.2 C483.2 C492.1 C505.1 R1040.1 U52.J13(VDD_IVA1) U52.K10(VDD_DSP1) U52.K11(VDD_DSP2) U52.K12(VDD_IVA2) U52.K13(VDD_IVA3) U52.L10(VDD_DSP3) U52.L11(VDD_DSP4) U52.L12(VDD_IVA4) U52.M10(VDD_DSP5) U52.M11(VDD_DSP6) U52.M12(VDD_IVA5) U52.M13(VDD_IVA6) U52.U11(VDD_GPU.5) U52.U12(VDD_GPU.6) U52.V10(VDD_GPU.2) U52.V11(VDD_GPU.3) U52.V14(VDD_GPU.7) U52.W10(VDD_GPU.1) U52.W11(VDD_GPU.4) U52.W13(VDD_GPU.8) ; also on sheet 56 57 59
J6_VDD_MPU: C91.2 C92.2 C93.2 C94.2 C95.2 C96.2 C356.1 C359.2 C360.2 C365.1 C366.1 C367.2 C368.2 C369.1 C370.2 C384.1 C385.1 C387.1 C389.1 C391.2 C392.2 C396.1 U52.K17(VDD_MPU.10) U52.K18(VDD_MPU.2) U52.L15(VDD_MPU.11) U52.L16(VDD_MPU.12) U52.L17(VDD_MPU.6) U52.L18(VDD_MPU.8) U52.L19(VDD_MPU.3) U52.M15(VDD_MPU.13) U52.M16(VDD_MPU.14) U52.M17(VDD_MPU.5) U52.M18(VDD_MPU.7) U52.N17(VDD_MPU.4) U52.N18(VDD_MPU.1) U52.P17(VDD_MPU.15) U52.P18(VDD_MPU.9) U52.R18(VDD_MPU.16) ; also on sheet 52 56 57 59
J6_VDDA_PHY: E10.3 ; also on sheet 58 64 71
J6_VDDA_PLL: C521.1 C522.1 E3.3 E4.3 E5.3 E6.3 U52.AD16(VDDA_OSC.1) U52.AE16(VDDA_OSC.2) ; also on sheet 58
J6_VDDSHV5: C104.1 C355.1 C436.1 C437.2 C438.1 C442.1 C443.1 C444.2 C445.1 C449.1 C450.2 C454.1 C455.2 C457.1 C464.1 C482.1 C484.1 C485.1 C493.1 C494.1 C496.1 C500.1 C502.1 C526.1 C542.2 C545.1 C700.1 R204.1 R799.2 U52.AB6(VDDSHV7.1) U52.AB7(VDDSHV7.2) U52.AD5(VDDSHV6.2) U52.AD7(VDDSHV6.4) U52.AE7(VDDSHV6.3) U52.AF5(VDDSHV6.1) U52.B6(VDDSHV2.1) U52.B23(VDDSHV3.9) U52.C24(VDDSHV4.1) U52.D10(VDDSHV2.5) U52.D16(VDDSHV3.4) U52.D22(VDDSHV3.8) U52.E3(VDDSHV1.1) U52.E5(VDDSHV1.4) U52.E10(VDDSHV2.4) U52.E16(VDDSHV3.3) U52.E22(VDDSHV3.7) U52.G4(VDDSHV1.2) U52.G5(VDDSHV1.3) U52.G15(VDDSHV3.2) U52.H8(VDDSHV1.5) U52.H9(VDDSHV1.6) U52.H10(VDDSHV2.2) U52.H11(VDDSHV2.3) U52.H15(VDDSHV3.1) U52.H16(VDDSHV3.6) U52.H18(VDDSHV3.5) U52.H19(VDDSHV3.10) U52.N4(VDDSHV10.2) U52.N5(VDDSHV10.4) U52.P10(VDDSHV10.6) U52.R7(VDDSHV10.5) U52.R10(VDDSHV10.7) U52.T4(VDDSHV10.1) U52.T5(VDDSHV10.3) U52.U10(VDDSHV9.3) U52.V12(VDDSHV5) U52.W4(VDDSHV9.1) U52.W5(VDDSHV9.2) U136.8(IN1) ; also on sheet 41 58 59
J6_VDDSHV8: C467.1 U52.W8(VDDSHV8.2) U52.Y8(VDDSHV8.1) ; also on sheet 30 58
MMC2_SELn: U136.3(D1) ; also on sheet 42 43 70
NC_P19: C516.1 U52.P19(NC)
NC_R20: C1055.1 U52.R20(NC)
NC_Y15: C1054.1 U52.Y15(NC)
NC_Y16: C512.1 U52.Y16(NC)
PCI_PORz: U61.2(A) ; also on sheet 36
PMIC_OFF: R204.2 R216.1 ; also on sheet 41 56
PMIC_RESET_OUT: U62.1(B) ; also on sheet 56
PORz: C550.1 C551.1 C552.1 R269.2 R670.1 R795.1 TP60.1(TP) U52.F22(PORZ) U61.4(Y)
RESETn: C553.1 C554.1 C555.1 TP59.1(TP) U52.E23(RESETN) U60.4(Y)
RSTOUTn: R256.2 R796.1 TP58.1(TP) U52.F23(RSTOUTN) ; also on sheet 3 26 28 29 34 35 40 56 59
VAYU_VDDA_CSI1.8: C1050.1 C1051.1 C1052.1 C1053.2 E10.1 U52.W12(VDDA_CSI)
VAYU_VDDA_DEBUG1.8: C414.2 C420.1 C427.1 C490.1 E4.1 U52.N11(VDDA_DEBUG) U52.N12(VDDA_DSP_IVA)
VAYU_VDDA_IVA1.8: C415.2 C422.1 C429.1 C497.1 E3.1 U52.R14(VDDA_GPU) U52.R17(VDDA_DDR)
VAYU_VDDA_MPU1.8: C413.1 C419.1 C426.1 C507.2 E5.1 U52.M14(VDDA_PER) U52.N16(VDDA_MPU_ABE)
VAYU_VDDA_VIDEO1.8: C412.2 C418.1 C425.1 C491.1 E6.1 U52.P14(VDDA_CORE_GMAC) U52.P15(VDDA_PLL_SPARE) U52.P16(VDDA_VIDEO)
VSYS_3V3: C145.1 C146.1 C573.1 U60.5(VCC) U61.5(VCC) U62.5(VCC) ; also on sheet 23 36 46 52 54 55 56 57 58
WAKEUP3: R620.1 TP55.1(TP) U52.AC16(WAKEUP3/sys_nirq1/gpio1_3/dcan2_rx) ; also on sheet 56
ZQ_DBYTE1: R694.1 U115.H8(ZQ)
ZQ_DBYTE2: R289.1 U69.H8(ZQ)
ZQ_DBYTE3: R695.1 U116.H8(ZQ)
ZQ_DBYTE4: R288.1 U68.H8(ZQ)
ZQ_DBYTE4_1: R693.1 U67.H8(ZQ)
N17034340: R216.2 U52.Y11(ON_OFF)
N22073920: R801.2 U136.4(ILIM)
N23034062: C123.2 C124.2 U52.AC14(VSSA_OSC1) Y5.2 Y5.4
N23034072: C106.1 U52.AD14(RTC_OSC_XO) Y3.1
N23034098: C113.1 U52.AE14(RTC_OSC_XI_CLKIN32) Y3.4
N23034254: C123.1 U52.AC15(XI_OSC1) Y5.1
N23034256: C124.1 U52.AC13(XO_OSC1) Y5.3
N23034287: C126.1 U52.AD15(X0_OSC0) Y6.2
N23034295: C128.1 U52.AE15(XI_OSC0) Y6.1
N23034297: C126.2 C128.2 U52.AF15(VSSA_OSC0)
N23313064: R1038.1 U52.E24(NC) U52.G22(NC) U52.G23(NC) U52.H20(NC) U52.H21(NC) U52.H22(NC) U52.J27(NC) U52.L20(NC) U52.L21(NC) U52.M20(NC) U52.M21(NC)
N23394964: C112.1 C466.1 C474.1 C495.1 C1056.2 C1057.2 R1040.2 U52.U18(NC) U52.U19(NC) U52.V18(NC) U52.V19(NC)
N24585716: R1087.1 U67.H9(ZQ1)
N24585804: R1088.1 U115.H9(ZQ1)
N24586106: R1089.1 U69.H9(ZQ1)
N24586409: R1090.1 U116.H9(ZQ1)
N24586714: R1091.1 U68.H9(ZQ1)
N25948424: U61.1(B) U62.4(Y)
N27151094: R269.1 U52.AF14(RTC_ISO)
N39334441: TP51.1 U52.K14(VPP)

Not connected (* = marked no-connect by the designer): U52 A27(IFORCE) B28(VSENSE) Y10(ATESTV); U67 A3(NC.1) A7(~{TDQS}); U68 A3(NC.1) A7(~{TDQS}); U69 A3(NC.1) A7(~{TDQS}); U115 A3(NC.1) A7(~{TDQS}); U116 A3(NC.1) A7(~{TDQS}); U136 1(STAT)*

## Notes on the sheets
sheet 11
- ON_OFF = 1 COMMANDS ALL NON-RTC DOMAINS TO BE ACTIVE
  ON_OFF = 0 COMMANDS ALL NON-RTC DOMAINS TO BE IN-ACTIVE
- Note: WAKEUP[3:0], including the
  GP1[x] functions, are
  input-only.
- ON RTC POWER DOMAIN
- ON RTC POWER DOMAIN
sheet 12
- CAPS INSTALLED FOR INTERNAL TESTING, 4 PLACES.
sheet 13
- D1=1, IN1 NOR BOOT
  D1=0,IN2 eMMC BOOT
- BOOT SWITCHES DEFAULT AS PULLUPS. SWITCH
  CLOSED IS PULL DOWN TO SELECT FUNCTION.
sheet 14
- VDDS18V
  CONNECTIONS FOR
  INTERNAL
  TESTING.
sheet 15
- INTERNAL TESTING.
sheet 16
- 1.8 VOLT
sheet 17
- 1.X VOLT
- 1.X VOLT
- 1.X VOLT
- 1.X VOLT
- INTERNAL TESTING.
- CAPACITANCE      SIZE
  .1uF             0201
  .22uF            0201
  .47uF            0201
  1uF              0201
  2.2uF            0402
  4.7uF            0402
  10uF             0402
  22uF             0603
- 1.X VOLT
sheet 19
- MEMORY 3
- MEMORY 1
- MEMORY 4
- ECC
- MEMORY 2
sheet 20
- ER3
sheet 21
- ER13
